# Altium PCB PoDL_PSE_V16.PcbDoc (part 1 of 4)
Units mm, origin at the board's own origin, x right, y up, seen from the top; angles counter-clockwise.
Board outline 155 x 86.5 mm, 4 copper layers (Top Layer, Signal Layer 2, Signal Layer 3, Bottom Layer), stack 1.586 mm thick; 431 components, 281 nets, 1286 pads, 864 vias.
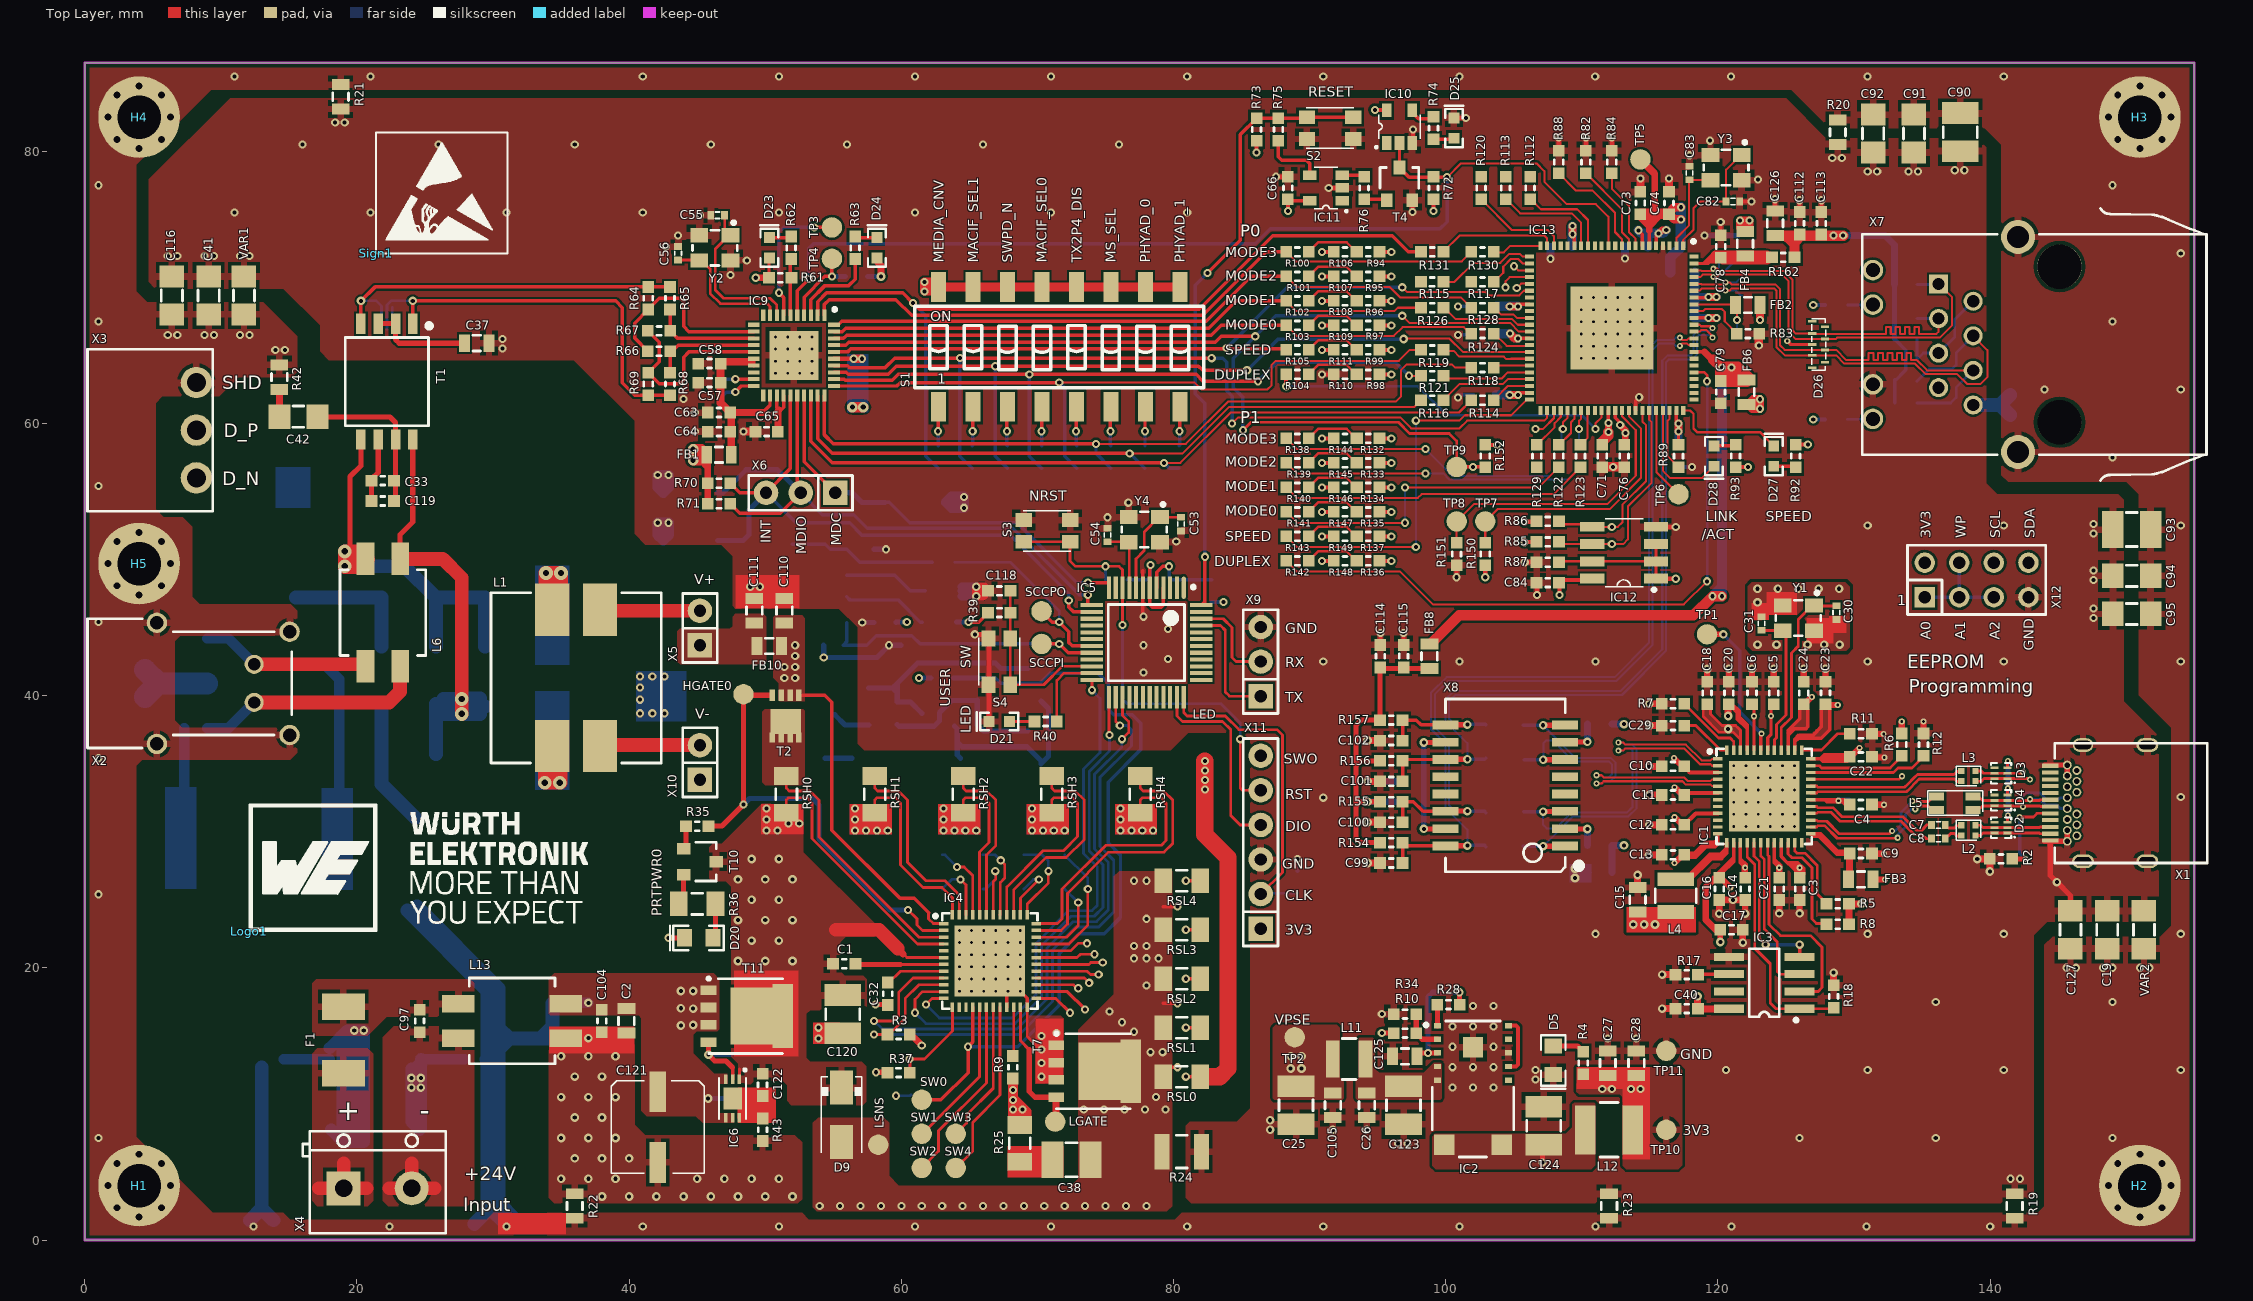
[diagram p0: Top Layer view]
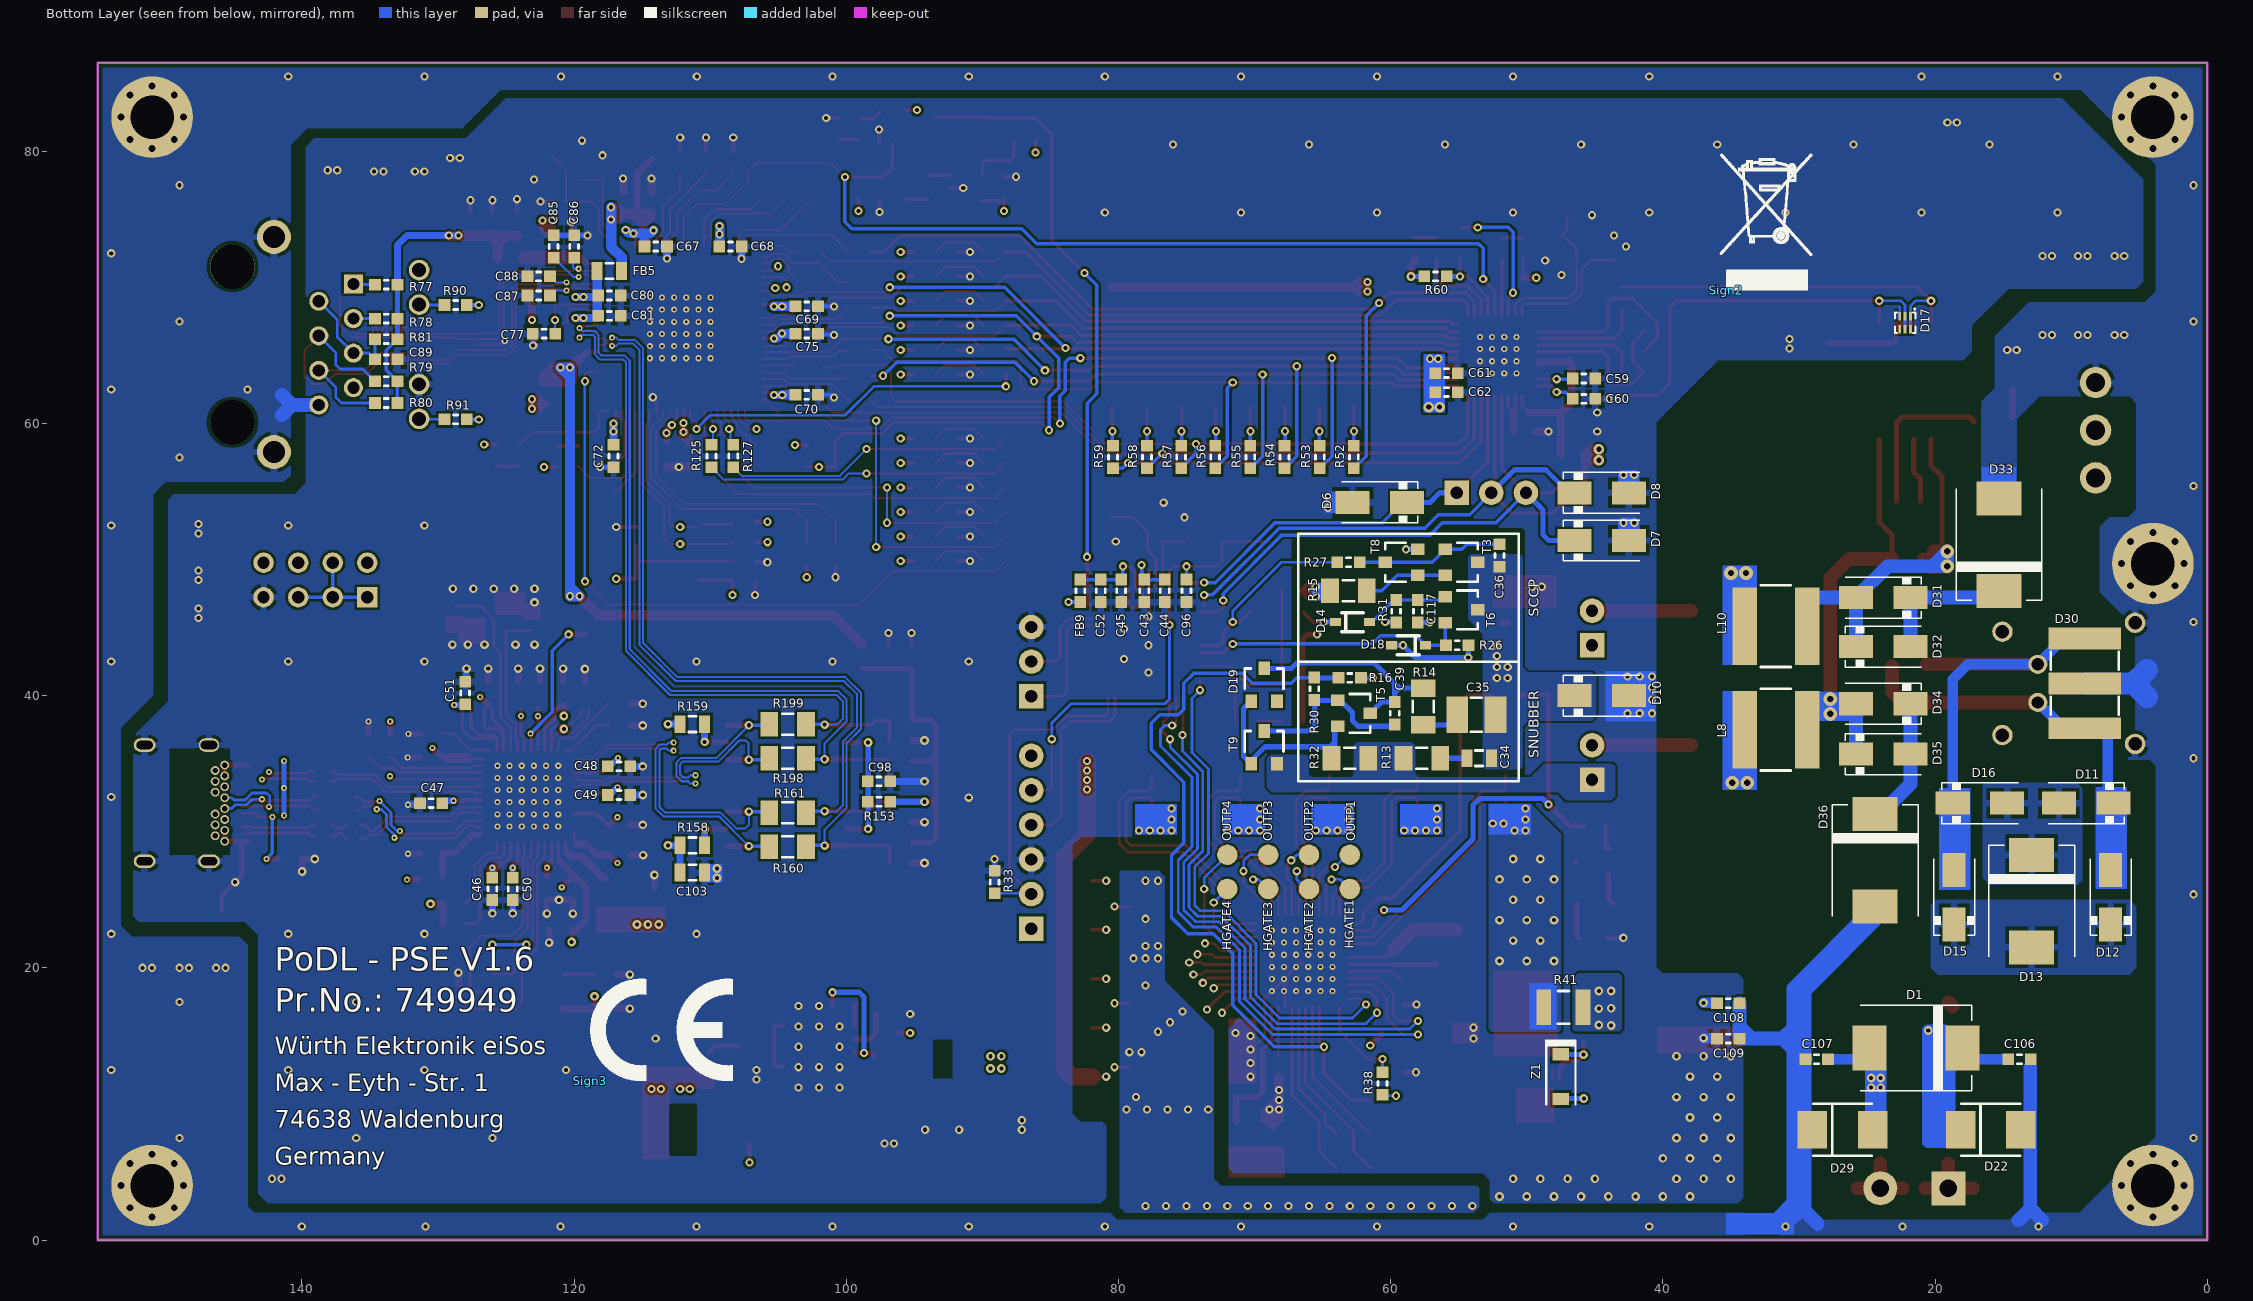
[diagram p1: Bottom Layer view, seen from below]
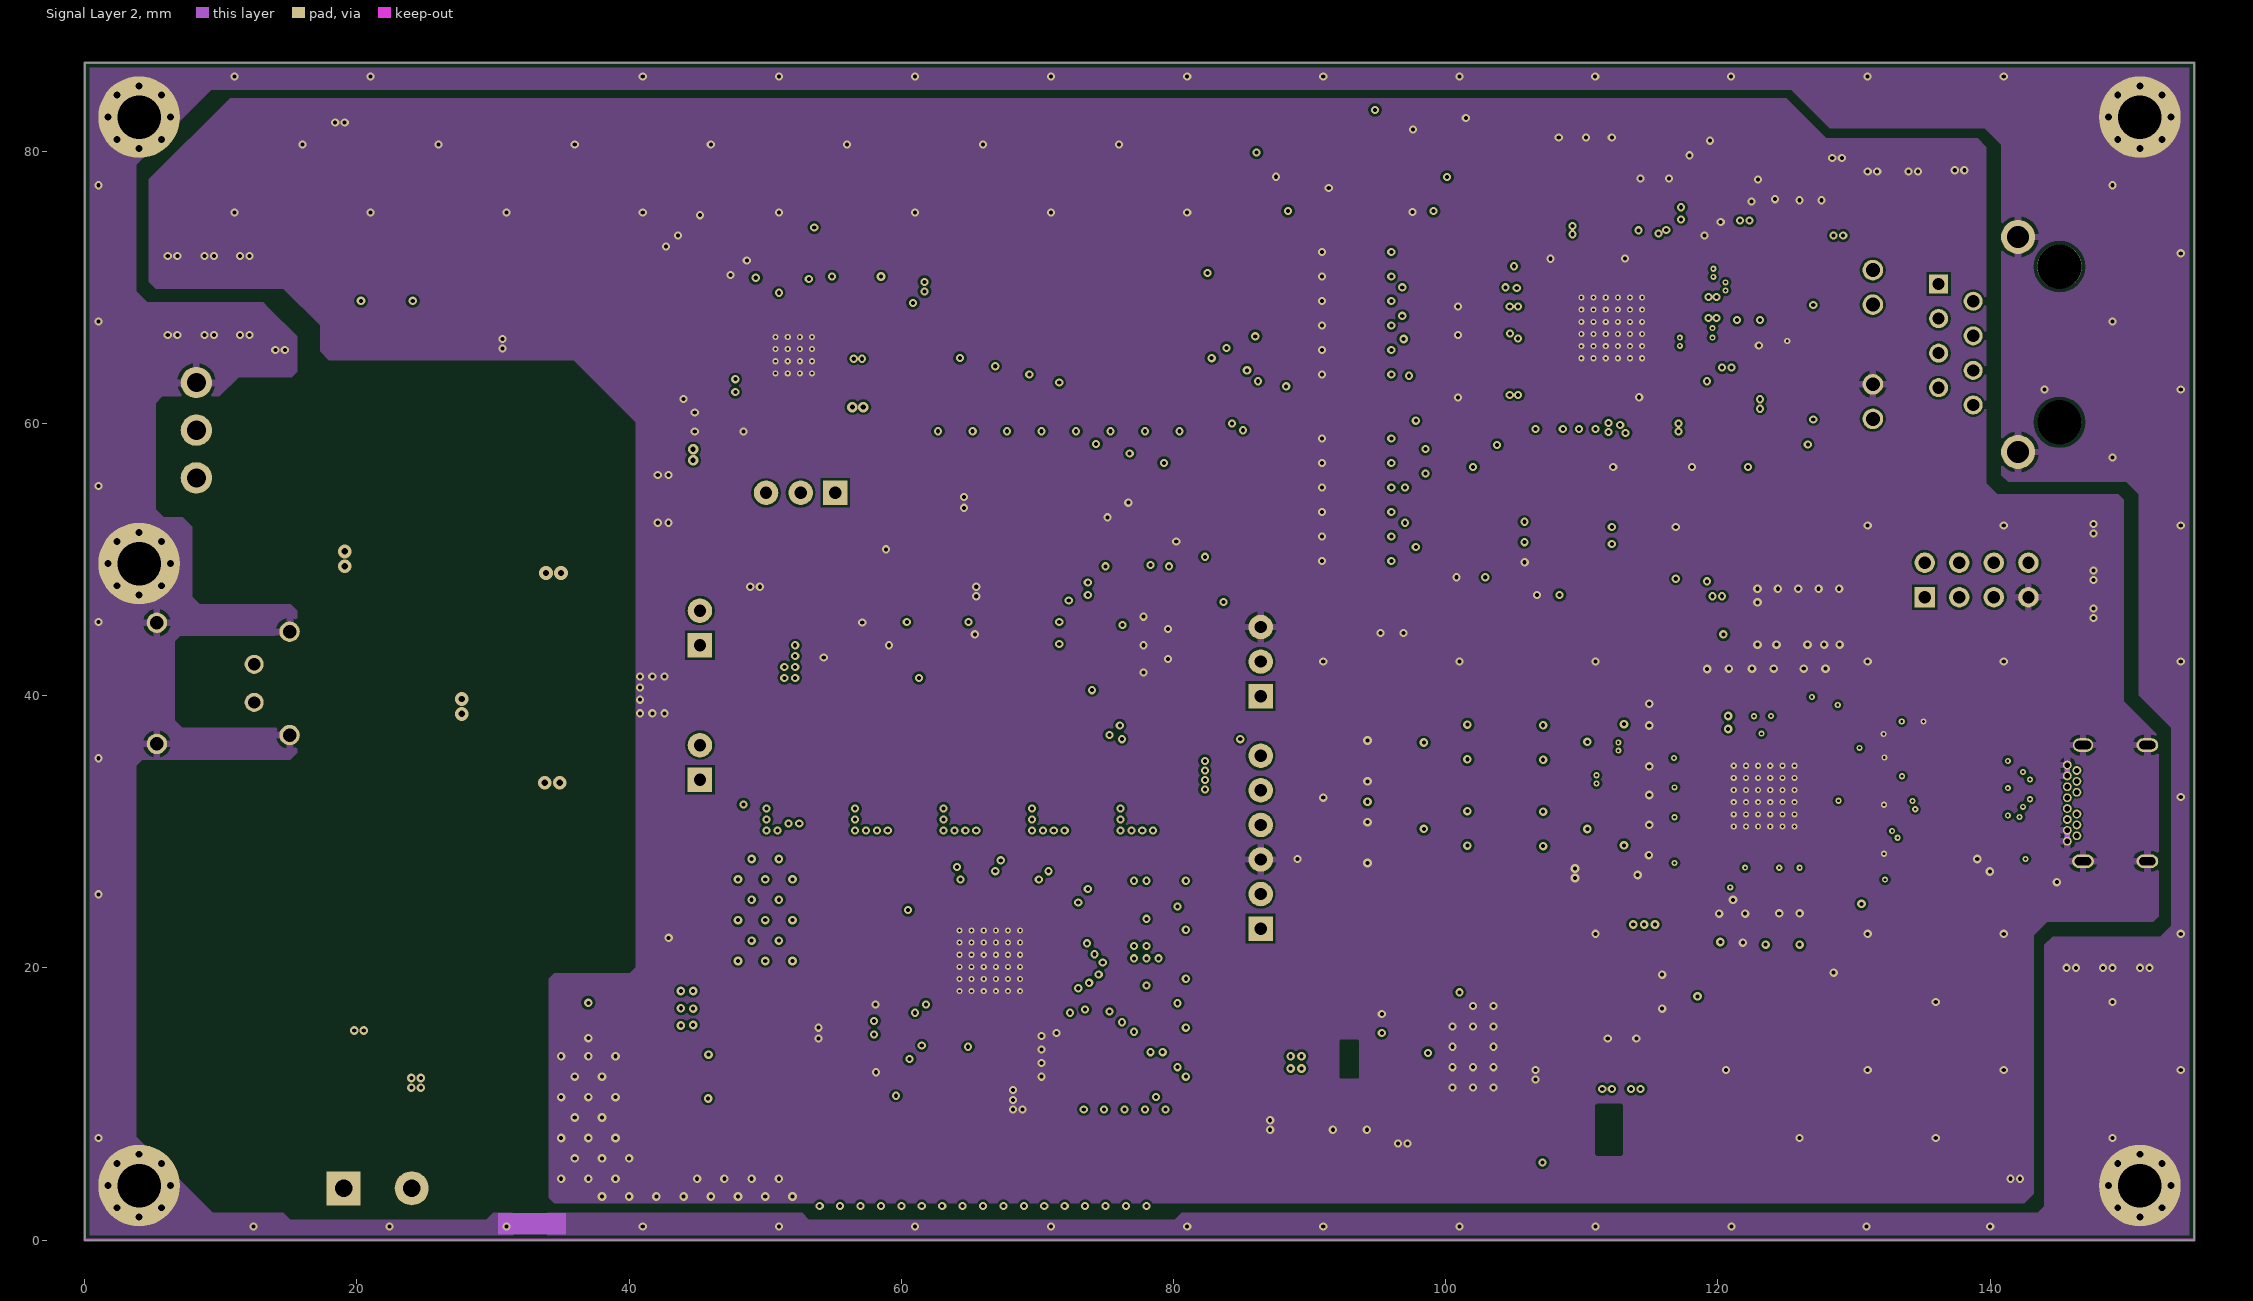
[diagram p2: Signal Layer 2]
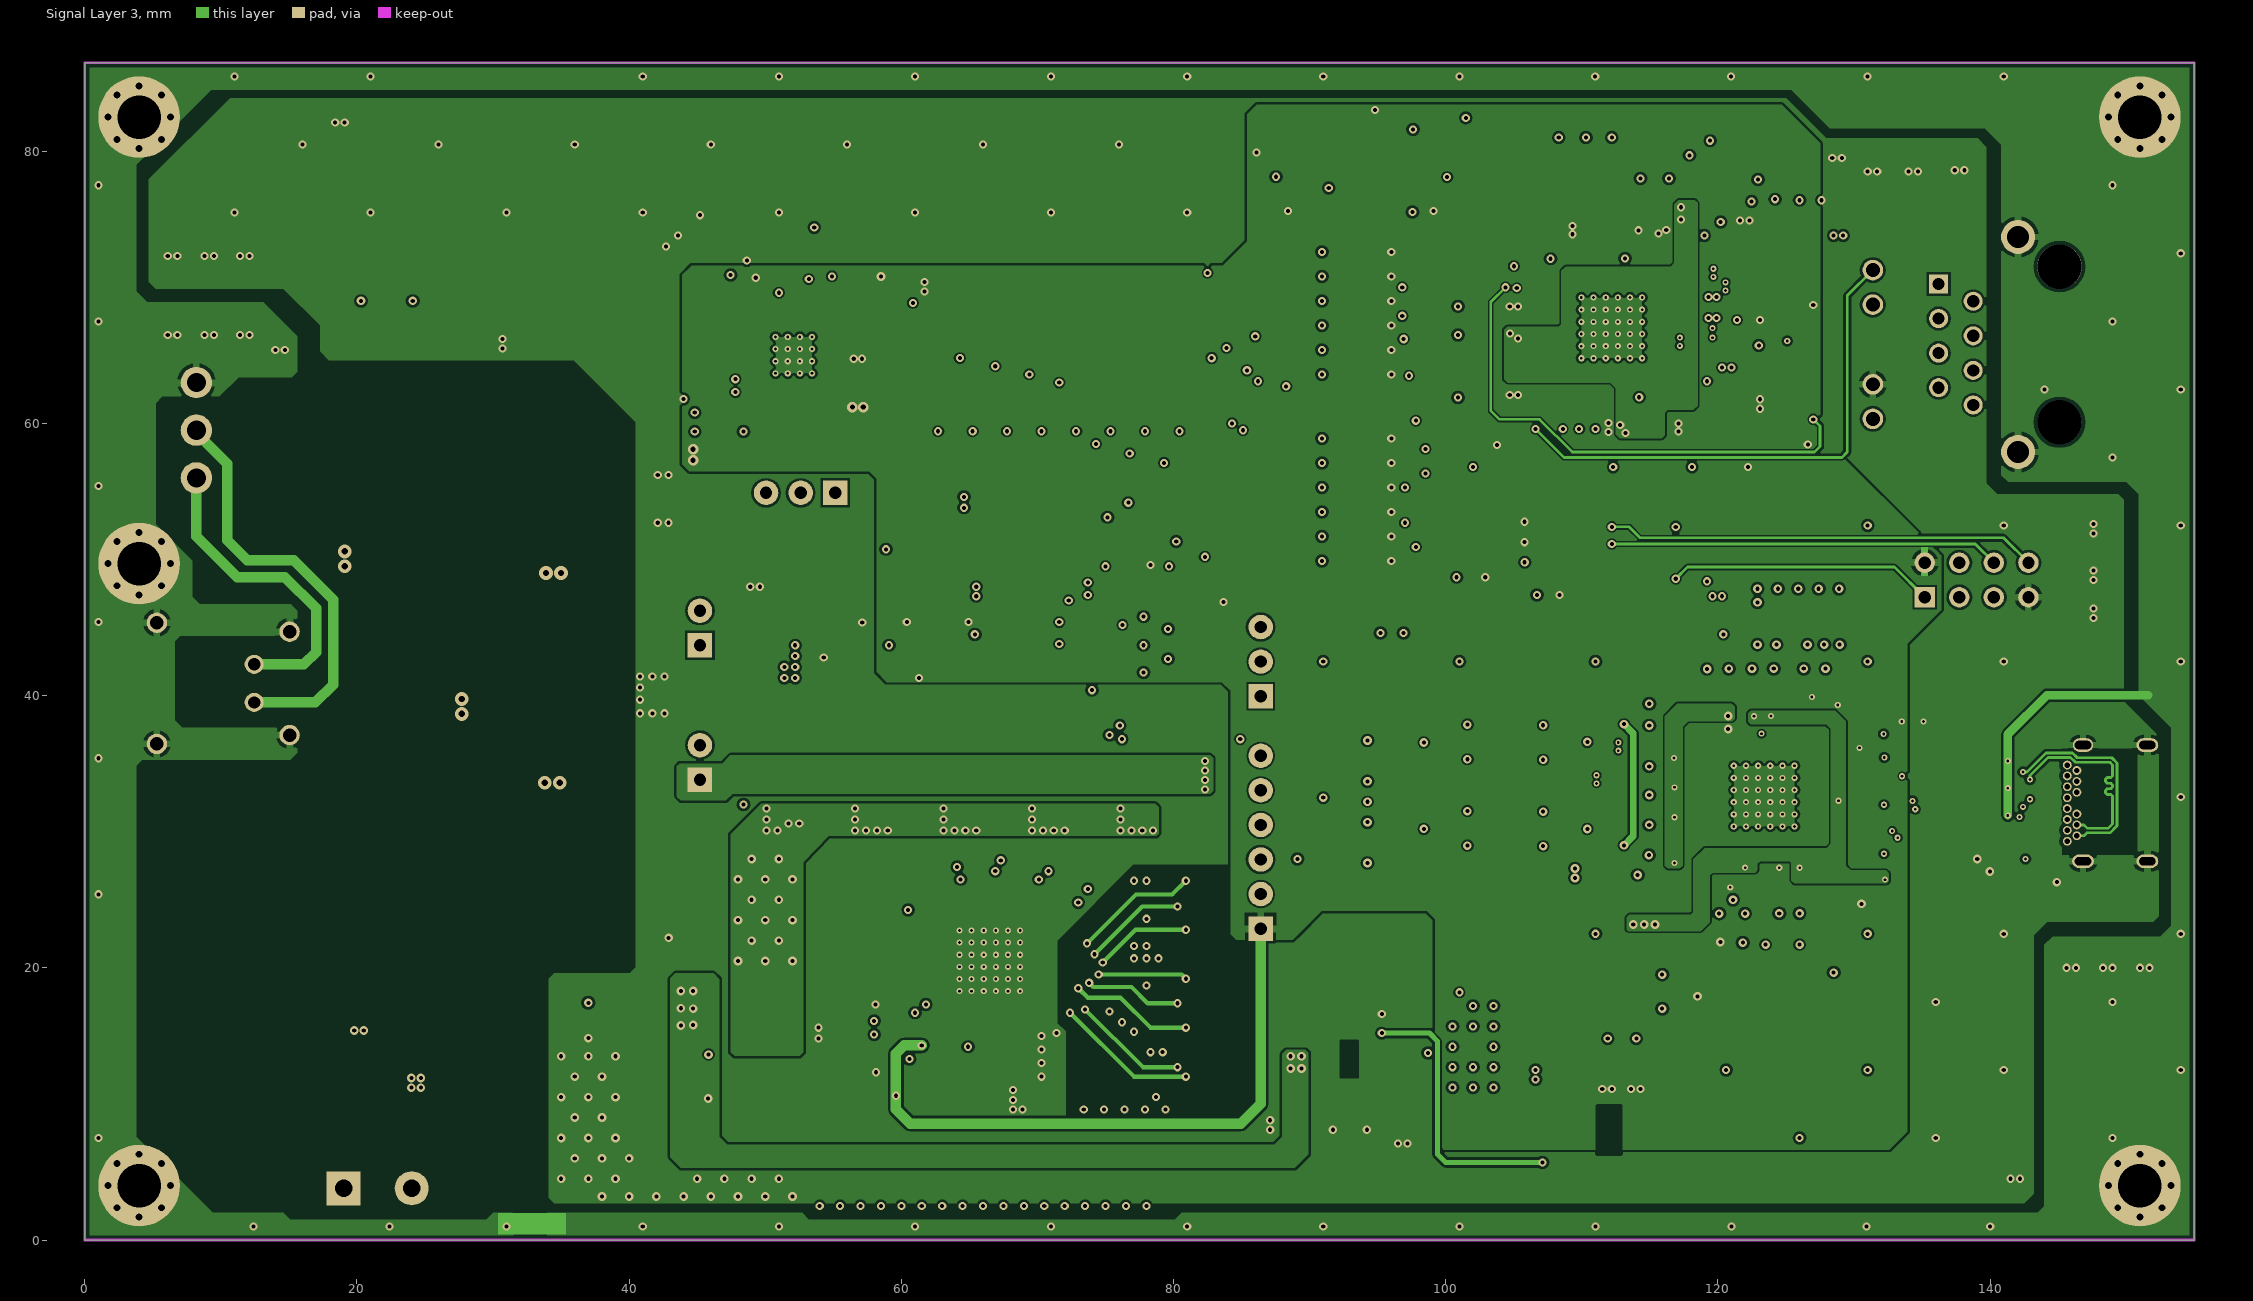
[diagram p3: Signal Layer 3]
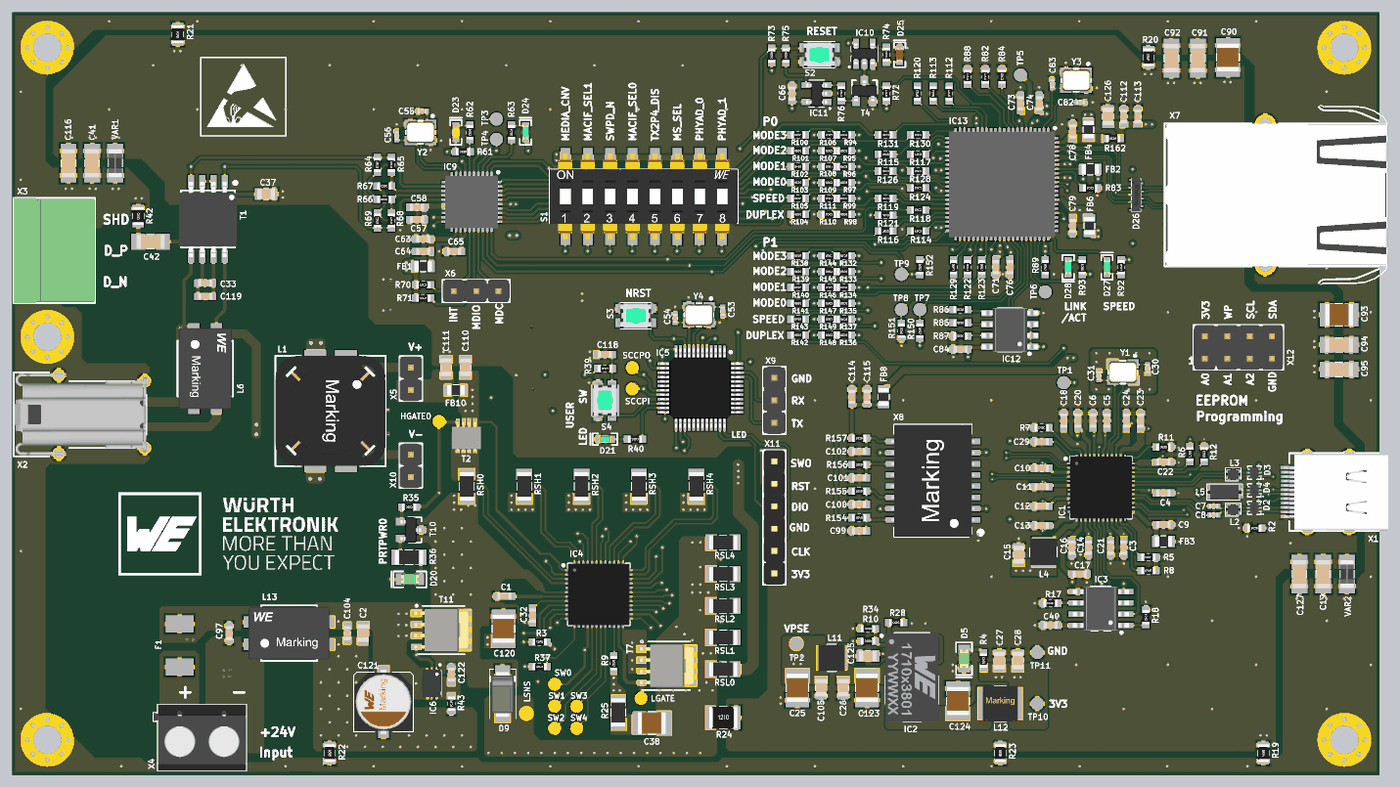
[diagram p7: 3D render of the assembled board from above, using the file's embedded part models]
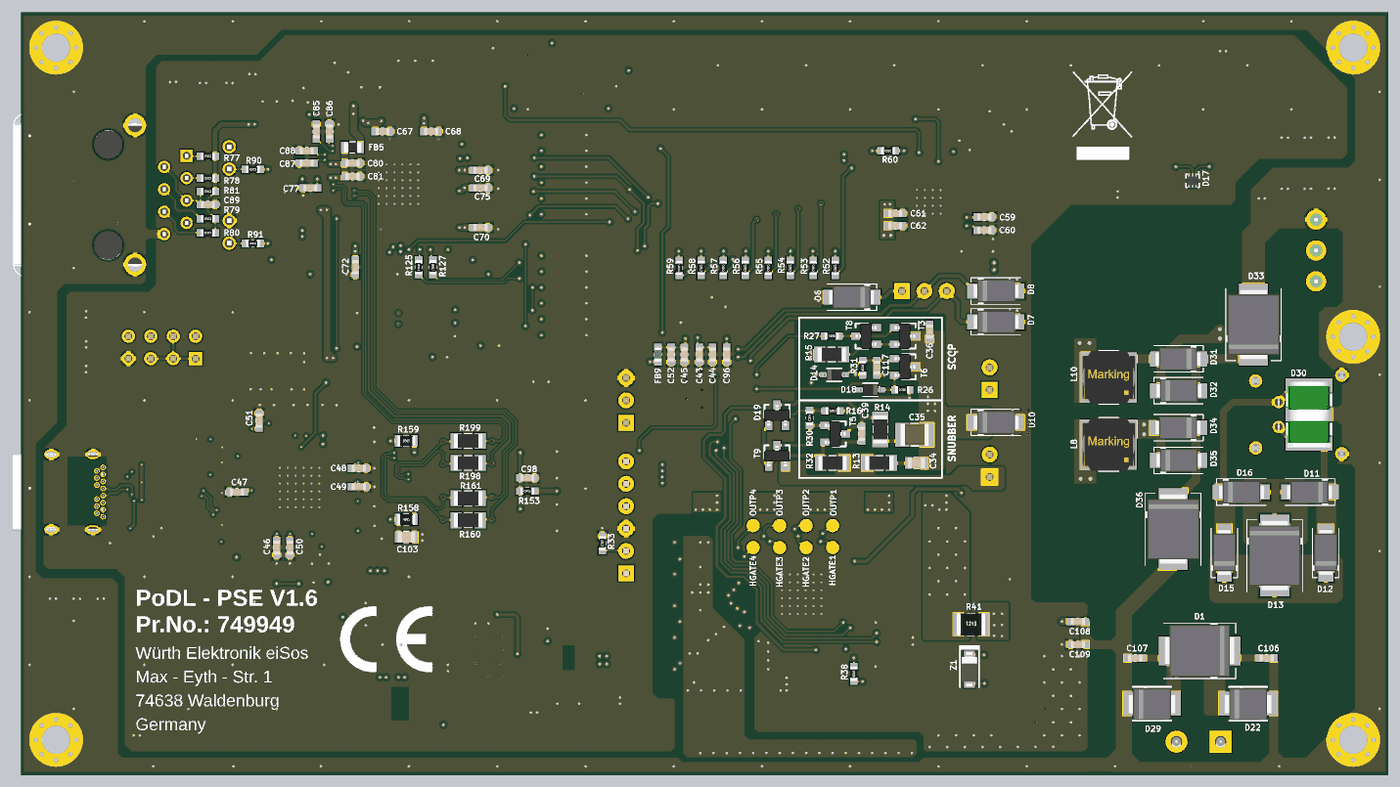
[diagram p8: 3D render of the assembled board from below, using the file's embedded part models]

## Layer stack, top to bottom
Top Solder: solder mask 0.01, Solder Resist, Dk 3.8
Top Layer: signal copper 0.035
Dielectric 1: prepreg 0.2104, 7628, Dk 4.6
Signal Layer 2: signal copper 0.0152
Dielectric 3: core 1.065, Core-009, Dk 4.6
Signal Layer 3: signal copper 0.0152
Dielectric 2: prepreg 0.2104, PP-006, Dk 4.6
Bottom Layer: signal copper 0.035
Bottom Solder: solder mask 0.01, Solder Resist, Dk 3.8

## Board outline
0,0 0,86.5 155,86.5 155,0

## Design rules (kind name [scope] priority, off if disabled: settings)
Clearance USB_to_SHIELD [InDifferentialPairClass('DiffPairs_USB') vs InNet('SHIELD')] p1: gap=0.152 ignorepadtopadclearanceinfootprint=FALSE
Clearance USB-C_Pad [InPadClass('USB-C')] p2: gap=0.127 ignorepadtopadclearanceinfootprint=FALSE
Clearance GND [InNet('GND')] p3: gap=0.178 ignorepadtopadclearanceinfootprint=FALSE
Clearance SHIELD_GND [InNet('SHIELD') vs InNet('GND')] p4: gap=0.483 ignorepadtopadclearanceinfootprint=FALSE
Clearance SHIELD_ALL [InNet('SHIELD')] p5: gap=0.254 ignorepadtopadclearanceinfootprint=FALSE
Clearance Keepout [OnLayer('Keep-Out Layer')] p6: gap=0.381 ignorepadtopadclearanceinfootprint=FALSE
Clearance [All] p7: gap=0.127 ignorepadtopadclearanceinfootprint=FALSE
ComponentClearance USB_Decoupling [InComponentClass('USB-Decoupling') vs InComponentClass('USB-Decoupling')] p1: gap=0 collisioncheckmode=3 verticalgap=0 showdistances=FALSE
ComponentClearance [All] p2: gap=0.254 collisioncheckmode=3 verticalgap=0.254 showdistances=FALSE
DiffPairsRouting DiffPairs_DADA_IN [InDifferentialPairClass('DiffPairs_DATA_IN')] p1: maxlimit=0.203 minlimit=0.203 mostfreqgap=0.203 toplayer_minwidth=0.254 toplayer_maxwidth=1.016 toplayer_prefwidth=0.254 midlayer1_minwidth=0.254 midlayer1_maxwidth=0.762 midlayer1_prefwidth=0.254 midlayer2_minwidth=0.254 midlayer2_maxwidth=0.762 midlayer2_prefwidth=0.254 bottomlayer_minwidth=0.254 bottomlayer_maxwidth=1.016 bottomlayer_prefwidth=0.254 maxuncoupledlength=12.7
DiffPairsRouting DiffPairs_USB [InDifferentialPairClass('DiffPairs_USB')] p2: maxlimit=0.254 minlimit=0.127 mostfreqgap=0.254 toplayer_maxgap=0.127 toplayer_prefgap=0.127 toplayer_minwidth=0.206 toplayer_maxwidth=0.206 toplayer_prefwidth=0.206 midlayer1_maxgap=0.127 midlayer1_prefgap=0.127 midlayer1_minwidth=0.206 midlayer1_maxwidth=0.206 midlayer1_prefwidth=0.206 midlayer2_mingap=0.254 midlayer2_minwidth=0.381 midlayer2_maxwidth=0.381 midlayer2_prefwidth=0.381 bottomlayer_maxgap=0.127 bottomlayer_prefgap=0.127 bottomlayer_minwidth=0.206 bottomlayer_maxwidth=0.206 bottomlayer_prefwidth=0.206 maxuncoupledlength=12.7
DiffPairsRouting DiffPairs_ETH [InDifferentialPairClass('DiffPairs_ETH')] p3: maxlimit=0.254 minlimit=0.127 mostfreqgap=0.254 toplayer_maxgap=0.127 toplayer_prefgap=0.127 toplayer_minwidth=0.154 toplayer_maxwidth=0.254 toplayer_prefwidth=0.154 midlayer1_maxgap=0.127 midlayer1_prefgap=0.127 midlayer1_minwidth=0.154 midlayer1_maxwidth=0.254 midlayer1_prefwidth=0.154 midlayer2_mingap=0.254 midlayer2_minwidth=0.381 midlayer2_maxwidth=0.381 midlayer2_prefwidth=0.381 bottomlayer_maxgap=0.127 bottomlayer_prefgap=0.127 bottomlayer_minwidth=0.154 bottomlayer_maxwidth=0.254 bottomlayer_prefwidth=0.154 maxuncoupledlength=12.7
HoleSize [All] p1: absolutevalues=TRUE maxlimit=5 minlimit=0.025 maxpercent=80.000 minpercent=20.000
MinimumSolderMaskSliver [All] p1 off: minsoldermaskwidth=0.254
NetAntennae [All] p1 off: netantennaetolerance=0
PlaneConnect [All] p1: pad.planeconnectstyle=Relief pad.reliefexpansion=0.508 pad.reliefentries=4 pad.reliefconductorwidth=0.381 pad.reliefairgap=0.203 via.planeconnectstyle=Direct via.reliefexpansion=0.508 via.reliefentries=4 via.reliefconductorwidth=0.254 via.reliefairgap=0.254
PolygonConnect Polygon_NetC124_1 [InNet('NetC124_1')] p1: connectstyle=Direct reliefconductorwidth=0.254 reliefentries=4 polygonreliefangle="90 Angle" airgapwidth=0.254
PolygonConnect Polygon_NetC26_1 [InNet('NetC26_1')] p2: connectstyle=Direct reliefconductorwidth=0.254 reliefentries=4 polygonreliefangle="90 Angle" airgapwidth=0.254
PolygonConnect Polygon_+24V_FILTER [InNet('+24V')] p3: connectstyle=Direct reliefconductorwidth=0.254 reliefentries=4 polygonreliefangle="90 Angle" airgapwidth=0.254
PolygonConnect Polygon_NetIC4_3 [InNet('NetIC4_3')] p4: connectstyle=Direct reliefconductorwidth=0.254 reliefentries=4 polygonreliefangle="90 Angle" airgapwidth=0.254
PolygonConnect Polygon_NetC111_2(OUTP0_FIL) [InNet('NetC111_2')] p5: connectstyle=Direct reliefconductorwidth=0.254 reliefentries=4 polygonreliefangle="90 Angle" airgapwidth=0.254
PolygonConnect Polygon_OUTP0 [InNet('OUTP0')] p6: connectstyle=Direct reliefconductorwidth=0.254 reliefentries=4 polygonreliefangle="90 Angle" airgapwidth=0.254
PolygonConnect Polygon_OUTM0 [InNet('OUTM0')] p7: connectstyle=Direct reliefconductorwidth=0.254 reliefentries=4 polygonreliefangle="90 Angle" airgapwidth=0.254
PolygonConnect Polygo_LSNS [InNet('LSNS')] p8: connectstyle=Direct reliefconductorwidth=0.254 reliefentries=4 polygonreliefangle="90 Angle" airgapwidth=0.254
PolygonConnect PolygonTransformer [InNetClass('Transformer')] p9: connectstyle=Direct reliefconductorwidth=0.254 reliefentries=4 polygonreliefangle="90 Angle" airgapwidth=0.254
PolygonConnect "Polygon_SHIELD_USB_Fix hole" [InPadClass('Fix_Hole') vs InNet('SHIELD_USB')] p10: thpad.connectstyle=Direct thpad.reliefconductorwidth=0.254 thpad.reliefentries=4 thpad.polygonreliefangle="90 Angle" thpad.airgapwidth=0.254 smdpad.connectstyle=Relief smdpad.reliefconductorwidth=0.508 smdpad.reliefentries=4 smdpad.polygonreliefangle="90 Angle" smdpad.airgapwidth=0.254 via.connectstyle=Direct via.reliefconductorwidth=0.254 via.reliefentries=4 via.polygonreliefangle="90 Angle" via.airgapwidth=0.254
PolygonConnect Poly_GND_OSC [InNamedPolygon('GND_OSC') vs InNet('GND')] p11: connectstyle=Direct reliefconductorwidth=0.254 reliefentries=4 polygonreliefangle="90 Angle" airgapwidth=0.254
PolygonConnect "Poly_SHIELD_Fix hole" [InPadClass('Fix_Hole') vs InNet('SHIELD')] p12: thpad.connectstyle=Direct thpad.reliefconductorwidth=0.254 thpad.reliefentries=4 thpad.polygonreliefangle="90 Angle" thpad.airgapwidth=0.254 smdpad.connectstyle=Relief smdpad.reliefconductorwidth=0.508 smdpad.reliefentries=4 smdpad.polygonreliefangle="90 Angle" smdpad.airgapwidth=0.254 via.connectstyle=Direct via.reliefconductorwidth=0.254 via.reliefentries=4 via.polygonreliefangle="90 Angle" via.airgapwidth=0.254
PolygonConnect Poly_SHIELD [All vs InNet('SHIELD')] p13: thpad.connectstyle=Relief thpad.reliefconductorwidth=0.508 thpad.reliefentries=4 thpad.polygonreliefangle="90 Angle" thpad.airgapwidth=0.254 smdpad.connectstyle=Relief smdpad.reliefconductorwidth=0.508 smdpad.reliefentries=4 smdpad.polygonreliefangle="90 Angle" smdpad.airgapwidth=0.254 via.connectstyle=Direct via.reliefconductorwidth=0.254 via.reliefentries=4 via.polygonreliefangle="90 Angle" via.airgapwidth=0.254
PolygonConnect [All] p14: thpad.connectstyle=Relief thpad.reliefconductorwidth=0.508 thpad.reliefentries=4 thpad.polygonreliefangle="90 Angle" thpad.airgapwidth=0.254 smdpad.connectstyle=Relief smdpad.reliefconductorwidth=0.508 smdpad.reliefentries=4 smdpad.polygonreliefangle="90 Angle" smdpad.airgapwidth=0.254 via.connectstyle=Direct via.reliefconductorwidth=0.254 via.reliefentries=4 via.polygonreliefangle="90 Angle" via.airgapwidth=0.254
RoutingVias [All] p1: holewidth=0.2 width=0.5 viastyle="Through Hole" minholewidth=0.2 minwidth=0.45 maxholewidth=0.711 maxwidth=1.27
SilkToSilkClearance [All] p1 off: silktosilkclearance=0.254
SilkToSolderMaskClearance [IsPad] p1 off: minsilkscreentomaskgap=0.254 clearancetoexposedcopper=TRUE
SolderMaskExpansion [All] p1: expansion=0.102
Width [All] p1: maxlimit=2.54 minlimit=0.127 preferedwidth=0.254 minimp=50.000000 maximp=50.000000 favimp=50.000000
22 further rules are at their usual default settings.

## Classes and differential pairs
component class USB-Decoupling: L6
component class U_01-PSE_Power_MCU: C1 C2 C25 C26 C27 C28 C32 C33 C34 C35 C36 C37 C38 C39 C41 C42 C43 C44 C45 C52 C53 C54 C96 C97 C104 C105 C106 C107 C108 C109 C110 C111 C116 C117 C118 C119 C120 C121 C122 C123 C124 C125 D1 D5 D9 D10 D11 D12 D13 D14 D15 D16 D17 D18 D19 D20 D21 D22 D29 D30 D31 D32 D33 D34 D35 D36 F1 FB9 FB10 H1 H2 H3 H4 H5 HGATE0 HGATE1 HGATE2 HGATE3 HGATE4 IC2 IC4 IC5 IC6 L1 L6 L8 L10 L11 L12 L13 LGATE Logo1 LSNS OUTP1 OUTP2 OUTP3 OUTP4 R3 R4 R9 R10 R13 R14 R15 R16 R19 R20 R21 R22 R23 R24 R25 R26 R27 R28 R30 R31 R32 R33 R34 R35 R36 R37 R38 R39 R40 R41 R42 R43 RSH0 RSH1 RSH2 RSH3 RSH4 RSL0 RSL1 RSL2 RSL3 RSL4 S3 S4 SCCPI SCCPO Sign1 Sign2 Sign3 SW0 SW1 SW2 SW3 SW4 T1 T2 T3 T5 T6 T7 T8 T9 T10 T11 TP2 TP10 TP11 VAR1 X2 X3 X4 X5 X9 X10 X11 Y4 Z1
differential pair class DiffPairs_DATA_IN: POWER/DATA
differential pair class DiffPairs_ETH: RXA TR0 TR1 TXA
differential pair class DiffPairs_USB: D USB2D USB2D1 USB3RX USB3RX1 USB3TX USB3TX1
component class U_04-LAN_to_USB-C: C3 C4 C5 C6 C7 C8 C9 C10 C11 C12 C13 C14 C15 C16 C17 C18 C19 C20 C21 C22 C23 C24 C29 C30 C31 C40 C46 C47 C48 C49 C50 C51 C98 C99 C100 C101 C102 C103 C114 C115 C127 D2 D3 D4 FB3 FB8 IC1 IC3 L2 L3 L4 L5 R2 R5 R6 R7 R8 R11 R12 R17 R18 R153 R154 R155 R156 R157 R158 R159 R160 R161 R198 R199 TP1 VAR2 X1 X8 Y1
component class U_03-LAN_3-Ports_Switch: C66 C67 C68 C69 C70 C71 C72 C73 C74 C75 C76 C77 C78 C79 C80 C81 C82 C83 C84 C85 C86 C87 C88 C89 C90 C91 C92 C93 C94 C95 C112 C113 C126 D25 D26 D27 D28 FB2 FB4 FB5 FB6 IC10 IC11 IC12 IC13 R72 R73 R74 R75 R76 R77 R78 R79 R80 R81 R82 R83 R84 R85 R86 R87 R88 R89 R90 R91 R92 R93 R94 R95 R96 R97 R98 R99 R100 R101 R102 R103 R104 R105 R106 R107 R108 R109 R110 R111 R112 R113 R114 R115 R116 R117 R118 R119 R120 R121 R122 R123 R124 R125 R126 R127 R128 R129 R130 R131 R132 R133 R134 R135 R136 R137 R138 R139 R140 R141 R142 R143 R144 R145 R146 R147 R148 R149 R150 R151 R152 R162 S2 T4 TP5 TP6 TP7 TP8 TP9 X7 X12 Y3
component class U_02-10BASE-T1L_PHY: C55 C56 C57 C58 C59 C60 C61 C62 C63 C64 C65 D6 D7 D8 D23 D24 FB1 IC9 R52 R53 R54 R55 R56 R57 R58 R59 R60 R61 R62 R63 R64 R65 R66 R67 R68 R69 R70 R71 S1 TP3 TP4 X6 Y2
pad class USB-C: X1-B1 X1-B2 X1-B3 X1-B4 X1-B5 X1-B6 X1-B7 X1-B8 X1-B9 X1-B10 X1-B11 X1-B12
pad class Fix_Hole: H1-0 H2-0 H3-0 H4-0 H5-0
differential pair USB3TX: +USB3TX_P -USB3TX_N
differential pair USB3TX1: +USB3TX1_P -USB3TX1_N
differential pair USB3RX: +USB3RX_P -USB3RX_N
differential pair USB3RX1: +USB3RX1_P -USB3RX1_N
differential pair USB2D: +USB2D_P -USB2D_N
differential pair USB2D1: +USB2D1_P -USB2D1_N
differential pair TXB: +TXB_P -TXB_N
differential pair TXA: +TXA_P -TXA_N
differential pair TR1: +TR1_P -TR1_N
differential pair TR0: +TR0_P -TR0_N
differential pair RXB: +RXB_P -RXB_N
differential pair RXA: +RXA_P -RXA_N
differential pair POWER/DATA: +POWER/DATA_P -POWER/DATA_N
differential pair D: +D_P -D_N

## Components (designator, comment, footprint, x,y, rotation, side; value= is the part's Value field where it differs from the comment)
C1 "885012206083" CC1608-0603 55.8,20.3 r0 top value=1nF
C2 "885012207103" CC2012-0805 39.8,16.1 r270 top value=1uF
C3 "885012206071" CC1608-0603 126,25.8 r270 top value=100nF
C4 "885012206071" CC1608-0603 130.5,32 r0 top value=100nF
C5 "885012206071" CC1608-0603 124.1,40.2 r90 top value=100nF
C6 "885012206071" CC1608-0603 122.5,40.2 r90 top value=100nF
C7 "885012105018" CC1005-0402 136.2,30.5 r180 top value=100nF
C8 "885012105018" CC1005-0402 136.2,29.5 r180 top value=100nF
C9 "885012206052" CC1608-0603 130.5,28.4 r0 top value=1uF
C10 "885012206071" CC1608-0603 116.7,34.8 r180 top value=100nF
C11 "885012206071" CC1608-0603 116.7,32.7 r180 top value=100nF
C12 "885012206071" CC1608-0603 116.7,30.5 r180 top value=100nF
C13 "885012206071" CC1608-0603 116.7,28.3 r180 top value=100nF
C14 "885012206071" CC1608-0603 122,25.8 r270 top value=100nF
C15 "885012107005" CC2012-0805 114.1,25 r270 top value=22uF
C16 "885012206071" CC1608-0603 120.1,25.8 r270 top value=100nF
C17 "885012106006" CC1608-0603 121,22.8 r180 top value=10uF
C18 "885012206052" CC1608-0603 119.2,40.2 r90 top value=1uF
C19 "885012208112" CC3216-1206 148.6,22.8 r270 top value=10nF
C20 "885012206052" CC1608-0603 120.8,40.2 r90 top value=1uF
C21 "885012206071" CC1608-0603 124.5,25.8 r270 top value=100nF
C22 "885012206071" CC1608-0603 130.5,35.5 r0 top value=100nF
C23 "885012206071" CC1608-0603 127.9,40.2 r90 top value=100nF
C24 "885012206071" CC1608-0603 126.3,40.2 r90 top value=100nF
C25 "885012209073" CC3225-1210 89,9.9 r270 top value=10uF
C26 "885012207098" CC2012-0805 94.2,9.9 r270 top value=100nF
C27 "885012207026" CC2012-0805 111.9,13 r90 top value=10uF
C28 "885012207026" CC2012-0805 114,13 r90 top value=10uF
C29 "885012206052" CC1608-0603 116.7,37.8 r180 top value=1uF
C30 "885012005056" CC1005-0402 128.7,46.1 r90 top value=15pF
C31 "885012005056" CC1005-0402 123.2,45.3 r270 top value=15pF
C32 "885012206024" CC1608-0603 59,18.1 r270 top value=470nF
C33 "885012206120" CC1608-0603 21.9,55.8 r0 top value=100nF
C34 "885012207098" CC2012-0805 53.5,35.4 r0 bottom value=100nF
C35 "885382209002" CC3225-1210 53.7,38.6 r0 bottom value=2.2uF
C36 "885012206085" CC1608-0603 52,50.3 r270 bottom value=2.2nF
C37 "885012207098" CC2012-0805 28.8,65.9 r0 top value=100nF
C38 "885382209002" CC3225-1210 72.5,5.9 r180 top value=2.2uF
C39 "885012206085" CC1608-0603 59.7,38.7 r90 bottom value=2.2nF
C40 "885012206071" CC1608-0603 117.7,17 r180 top value=100nF
C41 "885012208112" CC3216-1206 9.1,69.4 r90 top value=10nF
C42 "885342208021" CC3216-1206 15.7,60.5 r180 top value=10nF
C43 "885012106012" CC1608-0603 78.1,47.7 r270 bottom value=4.7uF
C44 "885012206071" CC1608-0603 76.6,47.7 r270 bottom value=100nF
C45 "885012206040" CC1608-0603 79.8,47.7 r270 bottom value=10nF
C46 "885012206071" CC1608-0603 126,25.8 r270 bottom value=100nF
C47 "885012206071" CC1608-0603 130.5,32.1 r0 bottom value=100nF
C48 "885012206071" CC1608-0603 116.7,34.8 r180 bottom value=100nF
C49 "885012206071" CC1608-0603 116.7,32.7 r180 bottom value=100nF
C50 "885012206071" CC1608-0603 124.5,25.8 r270 bottom value=100nF
C51 "885012206071" CC1608-0603 128,40.2 r90 bottom value=100nF
C52 "885012206052" CC1608-0603 81.3,47.7 r270 bottom value=1uF
C53 "885012005056" CC1005-0402 80.55,52.6 r90 top value=15pF
C54 "885012005056" CC1005-0402 75.15,51.8 r270 top value=15pF
C55 "885012005056" CC1005-0402 46.5,75.3 r0 top value=15pF
C56 "885012005056" CC1005-0402 43.6,72.5 r270 top value=15pF
C57 "885012206071" CC1608-0603 45.9,63 r180 top value=100nF
C58 "885012206040" CC1608-0603 45.9,64.4 r180 top value=10nF
C59 "885012206071" CC1608-0603 45.8,63.3 r180 bottom value=100nF
C60 "885012206052" CC1608-0603 45.8,61.8 r180 bottom value=1uF
C61 "885012206040" CC1608-0603 55.9,63.7 r180 bottom value=10nF
C62 "885012206071" CC1608-0603 55.9,62.3 r180 bottom value=100nF
C63 "885012206071" CC1608-0603 46.6,60.8 r180 top value=100nF
C64 "885012206040" CC1608-0603 46.6,59.4 r180 top value=10nF
C65 "885012206051" CC1608-0603 50.1,59.4 r180 top value=680nF
C66 "885012206071" CC1608-0603 88.4,77.3 r270 top value=100nF
C67 "885012206071" CC1608-0603 114,73 r180 bottom value=100nF
C68 "885012206071" CC1608-0603 108.5,73 r180 bottom value=100nF
C69 "885012206071" CC1608-0603 102.9,68.6 r180 bottom value=100nF
C70 "885012206071" CC1608-0603 102.9,62.1 r180 bottom value=100nF
C71 "885012206071" CC1608-0603 111.5,57.6 r270 top value=100nF
C72 "885012206071" CC1608-0603 117.1,57.6 r270 bottom value=100nF
C73 "885012206026" CC1608-0603 114.3,76.2 r270 top value=1uF
C74 "885012206081" CC1608-0603 116.4,76.2 r90 top value=470pF
C75 "885012206071" CC1608-0603 102.9,66.6 r180 bottom value=100nF
C76 "885012206071" CC1608-0603 113.1,57.6 r270 top value=100nF
C77 "885012206071" CC1608-0603 122.2,66.6 r0 bottom value=100nF
C78 "885012206071" CC1608-0603 120.2,73 r90 top value=100nF
C79 "885012206071" CC1608-0603 120.2,62.3 r270 top value=100nF
C80 "885012206071" CC1608-0603 117.4,69.4 r180 bottom value=100nF
C81 "885012206071" CC1608-0603 117.4,67.9 r180 bottom value=100nF
C82 "885012005056" CC1005-0402 121.1,76.3 r180 top value=15pF
C83 "885012005056" CC1005-0402 117.9,78.4 r270 top value=15pF
C84 "885012206071" CC1608-0603 107.5,48.3 r0 top value=100nF
C85 "885012006051" CC1608-0603 121.5,73 r90 bottom value=10pF
C86 "885012006051" CC1608-0603 120,73 r90 bottom value=10pF
C87 "885012006051" CC1608-0603 122.6,69.4 r0 bottom value=10pF
C88 "885012006051" CC1608-0603 122.6,70.8 r0 bottom value=10pF
C89 "885012206091" CC1608-0603 133.8,64.7 r180 bottom value=22nF
C90 "" CC3225-1210 137.8,81.4 r270 top value=TBE
C91 "" CC3216-1206 134.4,81.3 r270 top value=TBE
C92 "" CC3216-1206 131.4,81.3 r270 top value=TBE
C93 "" CC3225-1210 150.4,52.2 r180 top value=TBE
C94 "" CC3216-1206 150.4,48.8 r180 top value=TBE
C95 "" CC3216-1206 150.4,46 r180 top value=TBE
C96 "885012206071" CC1608-0603 75,47.7 r270 bottom value=100nF
C97 "885012206114" CC1608-0603 24.6,16.1 r270 top value=10nF
C98 "885012206091" CC1608-0603 97.6,33.7 r180 bottom value=22nF
C99 "885012006051" CC1608-0603 96,27.7 r180 top value=10pF
C100 "885012006051" CC1608-0603 96,30.7 r180 top value=10pF
C101 "885012006051" CC1608-0603 96,33.7 r180 top value=10pF
C102 "885012006051" CC1608-0603 96,36.7 r180 top value=10pF
C103 "885012207116" CC2012-0805 111.3,27 r180 bottom value=1nF
C104 "885012206114" CC1608-0603 38,16.1 r270 top value=10nF
C105 "885012207098" CC2012-0805 91.7,9.9 r270 top value=100nF
C106 "885012206114" CC1608-0603 13.8,13.279 r180 bottom value=10nF
C107 "885012206114" CC1608-0603 28.7,13.279 r0 bottom value=10nF
C108 "885012206114" CC1608-0603 35.2,17.4 r180 bottom value=10nF
C109 "885012206114" CC1608-0603 35.2,14.8 r180 bottom value=10nF
C110 "885342207005" CC2012-0805 51.4,46.25 r270 top value=10nF
C111 "885342207005" CC2012-0805 49.2,46.25 r270 top value=10nF
C112 "885012206093" CC1608-0603 126,74.7 r90 top value=47nF
C113 "885012206093" CC1608-0603 127.6,74.7 r90 top value=47nF
C114 "885012206093" CC1608-0603 95.2,42.9 r90 top value=47nF
C115 "885012206093" CC1608-0603 96.9,42.9 r90 top value=47nF
C116 "885012208112" CC3216-1206 6.4,69.4 r90 top value=10nF
C117 "" CC1608-0603 58,46.2 r270 bottom value=TBE
C118 "885012206071" CC1608-0603 67.2,47.7 r180 top value=100nF
C119 "885012206120" CC1608-0603 21.9,54.3 r0 top value=100nF
C120 "885012209073" CC3225-1210 55.7,16.6 r270 top value=10uF
C121 "865080643008" "SMT 6.3mmx5.5mm - WE" 42.1,8.3 r0 top value=22uF
C122 "885012206093" CC1608-0603 49.8,11.4 r270 top value=47nF
C123 "885012209048" CC3225-1210 96.9,9.9 r270 top value=4.7uF
C124 "885012209048" CC3225-1210 107.2,8.4 r90 top value=4.7uF
C125 "885012207051" CC2012-0805 97,13.5 r180 top value=1uF
C126 "885012007063" CC2012-0805 124.2,74.7 r90 top value=1nF
C127 "885012208112" CC3216-1206 145.9,22.8 r270 top value=10nF
D1 "824541331" SMC/DO-214AB 21.4,14.1 r180 bottom
D2 "824012823" "DFN1210-6L 1.2X1.0" 140.8,30.3 r90 top
D3 "824012823" "DFN1210-6L 1.2X1.0" 140.8,34.3 r90 top
D4 "824012823" "DFN1210-6L 1.2X1.0" 140.8,32.3 r90 top
D5 "150080VS75000" "LED2012 (0805) - Green" 107.9,13.2 r90 top value=Green
D6 "824500500" SMA/DO-214AC 60.8,54.2 r180 bottom
D7 "824500500" SMA/DO-214AC 44.5,51.4 r0 bottom
D8 "824500500" SMA/DO-214AC 44.5,54.9 r0 bottom
D9 "S1B-13-F" SMA/DO-214AC 55.6,9.2 r90 top
D10 "S1B-13-F" SMA/DO-214AC 44.5,40 r0 bottom
D11 "S1B-13-F" SMA/DO-214AC 8.9,32.1 r180 bottom
D12 "S1B-13-F" SMA/DO-214AC 7.1,25.2 r270 bottom
D13 "824541361" SMC/DO-214AB 12.9,24.9 r90 bottom
D14 "BAT54WS-7-F" SOD-323 62.8,45.4 r0 bottom value=BAT54WS
D15 "S1B-13-F" SMA/DO-214AC 18.6,25.2 r270 bottom
D16 "S1B-13-F" SMA/DO-214AC 16.7,32.1 r0 bottom
D17 "824012823" "DFN1210-6L 1.2X1.0" 22.2,67.4 r0 bottom
D18 "BAT54WS-7-F" SOD-323 58.7,43.7 r180 bottom value=BAT54WS
D19 "MMBD914LT1G" SOT-23 69.3,40.8 r180 bottom value=MMBD914L
D20 "150080VS75000" "LED2012 (0805) - Green" 45.1,22.2 r0 top value=Green
D21 "150060BS55040" "LED1608 (0603) - BLUE" 67.2,38.1 r0 top value=Blue
D22 "824520241" SMB/DO-214AA 15.9,8.1 r0 bottom
D23 "LTST-C190KSKT" "LED1608 (0603) - YELLOW" 50.3,72.9 r270 top value=Yellow
D24 "150060VS75020" "LED1608 (0603) - Green" 58.2,72.9 r270 top value=Green
D25 "150060SS75020" "LED1608 (0603) - Red" 100.6,81.7 r270 top value=Red
D26 "824014885" WE-TVS_824014885 127.4,65.8 r270 top
D27 "150060VS75020" "LED1608 (0603) - Green" 124.1,57.6 r270 top value=Green
D28 "150060VS75020" "LED1608 (0603) - Green" 119.7,57.6 r90 top value=Green
D29 "824520241" SMB/DO-214AA 26.8,8.1 r0 bottom
D30 "2038-15-SM-RPLF" 2038-XX 9,40.9 r90 bottom value=150V
D31 "S1D-13-F" SMA/DO-214AC 23.8,47.2 r180 bottom
D32 "S1D-13-F" SMA/DO-214AC 23.8,43.6 r0 bottom
D33 "824541361" SMC/DO-214AB 15.3,51.1 r270 bottom
D34 "S1D-13-F" SMA/DO-214AC 23.8,39.4 r180 bottom
D35 "S1D-13-F" SMA/DO-214AC 23.8,35.7 r0 bottom
D36 "824541361" SMC/DO-214AB 24.4,27.9 r90 bottom
F1 "0454002.MR" SET 19,14.7 r90 top
FB1 "742792031" CF2012-0805 46.6,57.7 r0 top value=300R@100MHz
FB2 "742792031" CF2012-0805 122.2,68.7 r180 top value=300R@100MHz
FB3 "742792031" CF2012-0805 130.5,26.5 r0 top value=300R
FB4 "742792031" CF2012-0805 122,73.2 r270 top value=300R@100MHz
FB5 "742792031" CF2012-0805 117.4,71.2 r180 bottom value=300R@100MHz
FB6 "742792031" CF2012-0805 122.1,62.3 r90 top value=300R@100MHz
FB8 "742792040" CF2012-0805 98.8,42.9 r90 top value=600R@100MHz
FB9 "742792625" CF1608-0603 82.8,47.7 r270 bottom value=120R
FB10 "742792031" CF2012-0805 50.3,43.65 r180 top value=300R@100MHz
H1 "Hole M3 with Vias" M3_VIA 4,4 r0 top
H2 "Hole M3 with Vias" M3_VIA 151,4 r0 top
H3 "Hole M3 with Vias" M3_VIA 151,82.5 r0 top
H4 "Hole M3 with Vias" M3_VIA 4,82.5 r0 top
H5 "Hole M3 with Vias" M3_VIA 4,49.7 r90 top
HGATE0 "PartNumber" "TESTPOINT 1.5mm"#1 48.4,40.1 r90 top value=1.5mm
HGATE1 "PartNumber" "TESTPOINT 1.5mm"#1 63,25.8 r90 bottom value=1.5mm
HGATE2 "PartNumber" "TESTPOINT 1.5mm"#1 66,25.8 r90 bottom value=1.5mm
HGATE3 "PartNumber" "TESTPOINT 1.5mm"#1 69,25.8 r90 bottom value=1.5mm
HGATE4 "PartNumber" "TESTPOINT 1.5mm"#1 72,25.8 r90 bottom value=1.5mm
IC1 "LAN7800/Y9X" "QFN-48 7x7MM" 123.4,32.6 r0 top value=LAN7800
IC2 "171033801" MAGI³C-VDRM_LGA-12EP 102,11.1 r270 top
IC3 "93AA66C-I/SN" SO-8N 123.4,18.9 r90 top
IC4 "LTC4296AUK-1#PBF" "QFN-48 7x7MM" 66.5,20.5 r0 top value=LTC4296AUK-1
IC5 "STM32G030C8T6" "QFP-48 7x7MM" 78,43.9 r270 top
IC6 "LTC4359CDCB#TRMPBF" "DFN-6 2X3_0.5" 47.6,10.4 r180 top value=LTC4359CDCB
IC9 "ADIN1100CCPZ-R7" "QFN-40 6x6MM" 52.1,65 r270 top value=ADIN1100CCPZ
IC10 "74LVC1G14GV,125" SOT-23-5 96.6,81.8 r0 top value=74LVC1G14GV
IC11 "TPS3125L30DBVR" SOT-23-5 91.2,77.3 r90 top value=TPS3125L30
IC12 "24FC512-I/SN" SO-8 113.1,50.5 r90 top value=24FC512
IC13 "LAN9355I/ML" "QFN-88 12X12MM" 112.2,67 r270 top value=LAN9355
L1 "744870471_(2)" "Inductor_WE-DD 1280" 36.1,41.3 r0 top value=2x470uH
L2 "7442335600" INDUCTOR_WE-CNSW-HF-0504 138.4,30.1 r180 top value="60R @ 100MHz"
L3 "7442335600" INDUCTOR_WE-CNSW-HF-0504 138.4,34.1 r180 top value="60R @ 100MHz"
L4 "74404032033" "Inductor_WE-LQS 3015" 116.9,25.3 r270 top value=3.3uH
L5 "744232090" INDUCTOR_WE-CNSW-1206 137.4,32.1 r180 top value="90R @ 100MHz"
L6 "744224" Inductor_WE-SL2 21.9,46.1 r270 top value=2x250uH
L8 "74404064220" "Inductor_WE-LQS 6045" 31.7,37.5 r180 bottom value=22uH
L10 "74404064220" "Inductor_WE-LQS 6045" 31.7,45.1 r180 bottom value=22uH
L11 "74404032220" "Inductor_WE-LQS 3015" 92.9,13.3 r0 top value=22uH
L12 "74404042047" Inductor_WE-LQS-4018 112,8.1 r0 top value=4.7uH
L13 "744222" Inductor_WE-SL2 31.4,16.1 r0 top value=2x1000uH
LGATE "PartNumber" "TESTPOINT 1.5mm"#1 71.3,8.7 r0 top value=1.5mm
Logo1 "Wurth_994x400" Wurth_994x400 12.1,22.7 r0 top
LSNS "PartNumber" "TESTPOINT 1.5mm"#1 58.3,7 r90 top value=1.5mm
OUTP1 "PartNumber" "TESTPOINT 1.5mm"#1 63,28.3 r90 bottom value=1.5mm
OUTP2 "PartNumber" "TESTPOINT 1.5mm"#1 66,28.3 r90 bottom value=1.5mm
OUTP3 "PartNumber" "TESTPOINT 1.5mm"#1 69,28.3 r90 bottom value=1.5mm
OUTP4 "PartNumber" "TESTPOINT 1.5mm"#1 72,28.3 r90 bottom value=1.5mm
R2 "RC0603FR-075K1L" CR1608-0603 140.8,28 r180 top value=5k1
R3 "RC0603FR-075K1L" CR1608-0603 59.8,15.1 r180 top value=5k1
R4 "560112116020" CR1608-0603 110.1,13 r90 top value=330R
R5 "560112116005" CR1608-0603 128.8,24.7 r180 top value=10k
R6 "560112116005" CR1608-0603 133.5,36.4 r270 top value=10k
R7 "560112116091" CR1608-0603 116.7,39.4 r180 top value=2k
R8 "RC0603FR-0710KL" CR1608-0603 128.8,23.2 r0 top value=10k
R9 "RC0603FR-0724K3L" CR1608-0603 68.2,12.7 r270 top value=24k3
R10 "RC0603FR-07402KL" CR1608-0603 97,15.2 r180 top value=402k
R11 "560112116040" CR1608-0603 130.5,37.2 r0 top value=12k
R12 "560112116005" CR1608-0603 135.1,36.4 r90 top value=10k
R13 "RC1206FR-0749R9L" CR3216-1206 57.7,35.4 r0 bottom value=49R9
R14 "560112132008" CR3216-1206 57.6,39.2 r90 bottom value=20R
R15 "RC1206FR-075R1L" CR3216-1206 63.1,47.7 r0 bottom value=5R1
R16 "RC0603FR-075K1L" CR1608-0603 63,41.3 r0 bottom value=5k1
R17 "560112116005" CR1608-0603 117.7,19.5 r180 top value=10k
R18 "560112116005" CR1608-0603 128.5,17.9 r90 top value=10k
R19 "RC0805JR-070RL" CR2012-0805 141.8,2.5 r270 top value=0R
R20 "RC0805JR-070RL" CR2012-0805 128.8,81.4 r90 top value=0R
R21 "RC0805JR-070RL" CR2012-0805 18.8,84 r90 top value=0R
R22 "RC0805JR-070RL" CR2012-0805 36,2.5 r270 top value=0R
R23 "RC0805JR-070RL" CR2012-0805 112,2.5 r270 top value=0R
R24 "RC1210FR-0749K9L" CR3225-1210 80.6,6.5 r0 top value=49k9
R25 "560112132002" CR3216-1206 68.7,7.1 r90 top value=1R
R26 "560112116004" CR1608-0603 55.1,43.7 r0 bottom value=100k
R27 "RC0603FR-075K1L" CR1608-0603 63.1,49.8 r0 bottom value=5k1
R28 "560112116017" CR1608-0603 100.2,17.3 r0 top value=5k6
R30 "560112116005" CR1608-0603 65.6,40.5 r270 bottom value=10k
R31 "560112116112" CR1608-0603 59.6,46.2 r90 bottom value=49k9
R32 "RC1206FR-075R1L" CR3216-1206 63,35.4 r180 bottom value=5R1
R33 "560112116004" CR1608-0603 89.1,26.3 r270 bottom value=100k
R34 "RC0603FR-07137KL" CR1608-0603 97,16.6 r180 top value=137k
R35 "560112116004" CR1608-0603 45,30.4 r0 top value=100k
R36 "560112132034" CR3216-1206 45,24.7 r180 top value=100k
R37 "560112116004" CR1608-0603 59.8,12.3 r0 top value=100k
R38 "RC0603FR-07100KL" CR1608-0603 60.6,11.5 r90 bottom value=100k
R39 "560112116006" CR1608-0603 67.2,46.1 r0 top value=4k7
R40 "560112116020" CR1608-0603 70.6,38.1 r180 top value=330R
R41 "" CR3225-1210 47.3,17.1 r180 bottom value=TBE
R42 "560112120020" CR2012-0805 14.3,63.4 r90 top value=100R
R43 "560112116014" CR1608-0603 49.8,8.1 r270 top value=1k
R52 "560112116006" CR1608-0603 62.7,57.525 r90 bottom value=4k7
R53 "560112116006" CR1608-0603 65.2,57.525 r90 bottom value=4k7
R54 "560112116006" CR1608-0603 67.8,57.525 r90 bottom value=4k7
R55 "560112116006" CR1608-0603 70.3,57.525 r90 bottom value=4k7
R56 "560112116006" CR1608-0603 72.9,57.525 r90 bottom value=4k7
R57 "560112116006" CR1608-0603 75.4,57.525 r90 bottom value=4k7
R58 "560112116006" CR1608-0603 77.9,57.525 r90 bottom value=4k7
R59 "560112116006" CR1608-0603 80.4,57.525 r90 bottom value=4k7
R60 "560112116006" CR1608-0603 56.7,70.8 r0 bottom value=4k7
R61 "560112116005" CR1608-0603 51.1,70.7 r180 top value=10k
R62 "560112116006" CR1608-0603 51.9,72.9 r270 top value=4k7
R63 "560112116005" CR1608-0603 56.6,72.9 r90 top value=10k
R64 "560112116133" CR1608-0603 41.4,69.2 r270 top value=49R9
R65 "RC0603FR-075K1L" CR1608-0603 43,69.2 r270 top value=5k1
R66 "560112116005" CR1608-0603 42.2,65.3 r0 top value=10k
R67 "560112116005" CR1608-0603 42.2,66.8 r180 top value=10k
R68 "RC0603FR-075K1L" CR1608-0603 43,62.9 r90 top value=5k1
R69 "560112116133" CR1608-0603 41.4,62.9 r90 top value=49R9
R70 "560112116038" CR1608-0603 46.6,55.6 r0 top value=1k5
R71 "560112116038" CR1608-0603 46.6,54.1 r0 top value=1k5
R72 "560112116006" CR1608-0603 99.1,77.3 r90 top value=4k7
R73 "560112116005" CR1608-0603 86.1,81.6 r270 top value=10k
R74 "560112116091" CR1608-0603 99.1,81.7 r270 top value=2k
R75 "560112116009" CR1608-0603 87.7,81.6 r270 top value=100R
R76 "560112116014" CR1608-0603 94,77.3 r270 top value=1k
R77 "560112116133" CR1608-0603 133.8,70.2 r180 bottom value=49R9
R78 "560112116133" CR1608-0603 133.8,67.7 r180 bottom value=49R9
R79 "560112116133" CR1608-0603 133.8,63.1 r180 bottom value=49R9
R80 "560112116133" CR1608-0603 133.8,61.5 r180 bottom value=49R9
R81 "RC0603FR-070RL" CR1608-0603 133.8,66.2 r180 bottom value=0R
R82 "560112116005" CR1608-0603 110.3,79.2 r90 top value=10k
R83 "RC0603FR-0712K1L" CR1608-0603 122.2,66.6 r0 top value=12k1
R84 "560112116005" CR1608-0603 112.2,79.2 r270 top value=10k
R85 "560112116091" CR1608-0603 107.5,51.3 r0 top value=2k
R86 "560112116091" CR1608-0603 107.5,52.8 r0 top value=2k
R87 "560112116006" CR1608-0603 107.5,49.8 r180 top value=4k7
R88 "560112116005" CR1608-0603 108.3,79.2 r90 top value=10k
R89 "560112116005" CR1608-0603 117.1,57.6 r270 top value=10k
R90 "560112116020" CR1608-0603 128.7,68.7 r180 bottom value=330R
R91 "560112116020" CR1608-0603 128.7,60.3 r180 bottom value=330R
R92 "560112116020" CR1608-0603 125.7,57.6 r270 top value=330R
R93 "560112116020" CR1608-0603 121.3,57.6 r90 top value=330R
R94 "RC0603FR-070RL" CR1608-0603 94.3,72.6 r0 top value=0R
R95 "RC0603FR-070RL" CR1608-0603 94.3,70.8 r0 top value=0R
R96 "RC0603FR-070RL" CR1608-0603 94.3,69 r0 top value=0R
R97 "RC0603FR-070RL" CR1608-0603 94.3,67.2 r0 top value=0R
R98 "RC0603FR-070RL" CR1608-0603 94.3,63.6 r0 top value=0R
R99 "RC0603FR-070RL" CR1608-0603 94.3,65.4 r0 top value=0R
R100 "560112116005" CR1608-0603 89.1,72.6 r0 top value=10k
R101 "560112116005" CR1608-0603 89.1,70.8 r0 top value=10k
R102 "560112116005" CR1608-0603 89.1,69 r0 top value=10k
R103 "560112116005" CR1608-0603 89.1,67.2 r0 top value=10k
R104 "560112116005" CR1608-0603 89.1,63.6 r0 top value=10k
R105 "560112116005" CR1608-0603 89.1,65.4 r0 top value=10k
R106 "RC0603FR-070RL" CR1608-0603 92.6,72.6 r0 top value=0R
R107 "RC0603FR-070RL" CR1608-0603 92.6,70.8 r0 top value=0R
R108 "RC0603FR-070RL" CR1608-0603 92.6,69 r0 top value=0R
R109 "RC0603FR-070RL" CR1608-0603 92.6,67.2 r0 top value=0R
R110 "RC0603FR-070RL" CR1608-0603 92.6,63.6 r0 top value=0R
R111 "RC0603FR-070RL" CR1608-0603 92.6,65.4 r0 top value=0R
R112 "560112116034" CR1608-0603 106.2,77.3 r90 top value=33R
R113 "560112116034" CR1608-0603 104.4,77.3 r90 top value=33R
R114 "560112116034" CR1608-0603 102.7,61.7 r0 top value=33R
R115 "560112116034" CR1608-0603 99,70.4 r180 top value=33R
R116 "560112116034" CR1608-0603 99,61.7 r0 top value=33R
R117 "560112116034" CR1608-0603 102.7,70.4 r180 top value=33R
R118 "560112116034" CR1608-0603 102.7,64.1 r0 top value=33R
R119 "560112116034" CR1608-0603 99,65.4 r0 top value=33R
R120 "560112116034" CR1608-0603 102.6,77.3 r90 top value=33R
R121 "560112116034" CR1608-0603 99,63.5 r0 top value=33R
R122 "560112116034" CR1608-0603 108.3,57.6 r270 top value=33R
R123 "560112116034" CR1608-0603 109.9,57.6 r270 top value=33R
R124 "560112116034" CR1608-0603 102.7,66.6 r0 top value=33R
R125 "560112116034" CR1608-0603 109.9,57.6 r270 bottom value=33R
R126 "560112116034" CR1608-0603 99,68.5 r0 top value=33R
R127 "560112116034" CR1608-0603 108.3,57.6 r270 bottom value=33R
R128 "560112116034" CR1608-0603 102.7,68.5 r0 top value=33R
R129 "560112116034" CR1608-0603 106.7,57.6 r270 top value=33R
R130 "560112116034" CR1608-0603 102.7,72.6 r0 top value=33R
R131 "560112116034" CR1608-0603 99,72.6 r0 top value=33R
R132 "RC0603FR-070RL" CR1608-0603 94.3,58.9 r0 top value=0R
R133 "RC0603FR-070RL" CR1608-0603 94.3,57.1 r0 top value=0R
R134 "RC0603FR-070RL" CR1608-0603 94.3,55.3 r0 top value=0R
R135 "RC0603FR-070RL" CR1608-0603 94.3,53.5 r0 top value=0R
R136 "RC0603FR-070RL" CR1608-0603 94.3,49.9 r0 top value=0R
R137 "RC0603FR-070RL" CR1608-0603 94.3,51.7 r0 top value=0R
R138 "560112116005" CR1608-0603 89.1,58.9 r0 top value=10k
R139 "560112116005" CR1608-0603 89.1,57.1 r0 top value=10k
R140 "560112116005" CR1608-0603 89.1,55.3 r0 top value=10k
R141 "560112116005" CR1608-0603 89.1,53.5 r0 top value=10k
R142 "560112116005" CR1608-0603 89.1,49.9 r0 top value=10k
R143 "560112116005" CR1608-0603 89.1,51.7 r0 top value=10k
R144 "RC0603FR-070RL" CR1608-0603 92.6,58.9 r0 top value=0R
R145 "RC0603FR-070RL" CR1608-0603 92.6,57.1 r0 top value=0R
R146 "RC0603FR-070RL" CR1608-0603 92.6,55.3 r0 top value=0R
R147 "RC0603FR-070RL" CR1608-0603 92.6,53.5 r0 top value=0R
R148 "RC0603FR-070RL" CR1608-0603 92.6,49.9 r0 top value=0R
R149 "RC0603FR-070RL" CR1608-0603 92.6,51.7 r0 top value=0R
R150 "560112116038" CR1608-0603 102.9,50.4 r270 top value=1k5
R151 "560112116005" CR1608-0603 100.8,50.4 r90 top value=10k
R152 "560112116005" CR1608-0603 102.9,57.6 r270 top value=10k
R153 "RC0603FR-070RL" CR1608-0603 97.6,32.2 r180 bottom value=0R
R154 "560112116133" CR1608-0603 96,29.2 r180 top value=49R9
R155 "560112116133" CR1608-0603 96,32.2 r180 top value=49R9
R156 "560112116133" CR1608-0603 96,35.2 r180 top value=49R9
R157 "560112116133" CR1608-0603 96,38.2 r180 top value=49R9
R158 "RC0805FR-0775RL" CR2012-0805 111.3,29 r180 bottom value=75R
R159 "RC0805FR-0775RL" CR2012-0805 111.3,37.9 r180 bottom value=75R
R160 "CRCW12060000Z0EA" CR3216-1206 104.3,28.9 r180 bottom value=0R
R161 "CRCW12060000Z0EA" CR3216-1206 104.3,31.4 r180 bottom value=0R
R162 "RC0603FR-070RL" CR1608-0603 124.8,72.2 r0 top value=0R
R198 "CRCW12060000Z0EA" CR3216-1206 104.3,35.4 r180 bottom value=0R
R199 "CRCW12060000Z0EA" CR3216-1206 104.3,37.9 r180 bottom value=0R
RSH0 "RL1206FR-070R24L" CR3216-1206 51.55,32.75 r90 top value=0R24
RSH1 "CRCW12060000Z0EA" CR3216-1206 58.05,32.75 r90 top value=0R
RSH2 "CRCW12060000Z0EA" CR3216-1206 64.55,32.75 r90 top value=0R
RSH3 "CRCW12060000Z0EA" CR3216-1206 71.05,32.75 r90 top value=0R
RSH4 "CRCW12060000Z0EA" CR3216-1206 77.55,32.75 r90 top value=0R
RSL0 "RL1206FR-070R062L" CR3216-1206 80.6,12 r0 top value=0R062
RSL1 "CRCW12060000Z0EA" CR3216-1206 80.6,15.6 r0 top value=0R
RSL2 "CRCW12060000Z0EA" CR3216-1206 80.6,19.2 r0 top value=0R
RSL3 "CRCW12060000Z0EA" CR3216-1206 80.6,22.8 r0 top value=0R
RSL4 "CRCW12060000Z0EA" CR3216-1206 80.6,26.4 r0 top value=0R
S1 "418121270808" 418121270808 71.6,65.625 r0 top
S2 "434153017835" 434153017835 91.5,81.7 r180 top
S3 "434153017835" 434153017835 70.7,52.1 r180 top
S4 "434153017835" 434153017835 67.2,42.5 r270 top
SCCPI "PartNumber" "TESTPOINT 1.5mm"#1 70.3,43.8 r90 top value=1.5mm
SCCPO "PartNumber" "TESTPOINT 1.5mm"#1 70.3,46.2 r90 top value=1.5mm
Sign1 "ESD_380x350" ESD_380x351 21.4,72.496 r0 top
Sign2 "WEEE_275x400" WEEE_275x400 35.34,69.767 r180 bottom
Sign3 "CE_412x295" CE_412x295 118.8,11.7 r180 bottom
SW0 "PartNumber" "TESTPOINT 1.5mm"#1 61.5,10.3 r90 top value=1.5mm
SW1 "PartNumber" "TESTPOINT 1.5mm"#1 61.5,7.8 r90 top value=1.5mm
SW2 "PartNumber" "TESTPOINT 1.5mm"#1 61.5,5.3 r90 top value=1.5mm
SW3 "PartNumber" "TESTPOINT 1.5mm"#1 64,7.8 r90 top value=1.5mm
SW4 "PartNumber" "TESTPOINT 1.5mm"#1 64,5.3 r90 top value=1.5mm
T1 "749070011" 749070011_WE-PoDL 22.2,63.07 r180 top
T2 "PSMN075-100MSEX" "LFPAK33 (SOT1210)" 51.5,38.1 r180 top
T3 "BSS123LT1G" SOT-23 54.8,49.8 r270 bottom value=BSS123
T4 "BSS138LT1G" SOT-23 96.6,77.6 r0 top
T5 "BSS123LT1G" SOT-23 62.7,38.7 r270 bottom value=BSS123
T6 "MMBTA06LT1G" SOT-23 54.8,46.3 r270 bottom value=MMBTA06L
T7 "PSMN020-100YS,115" "LFPAK56 (SOT669)" 74.1,12.4 r270 top value=PSMN020-100YS
T8 "MMBT3904LT1G" SOT-23 59.2,49.8 r90 bottom value=MMBT3904
T9 "MMBT3904LT1G" SOT-23 69.3,36.2 r180 bottom value=MMBT3904
T10 "BSS123LT1G" SOT-23 45.2,27.8 r270 top value=BSS123
T11 "BUK7Y53-100B,115" "LFPAK56 (SOT669)" 48.55,16.45 r270 top value=BUK7Y53-100B
TP1 "PartNumber" "TESTPOINT 1.5mm"#2 119.2,44.5 r0 top value=1.5mm
TP2 "PartNumber" "TESTPOINT 1.5mm"#2 88.9,14.9 r90 top value=1.5mm
TP3 "PartNumber" "TESTPOINT 1.5mm"#2 54.9,74.4 r90 top value=1.5mm
TP4 "PartNumber" "TESTPOINT 1.5mm"#2 54.9,72.1 r90 top value=1.5mm
TP5 "PartNumber" "TESTPOINT 1.5mm"#2 114.3,79.4 r90 top value=1.5mm
TP6 "PartNumber" "TESTPOINT 1.5mm"#2 117.1,54.8 r90 top value=1.5mm
TP7 "PartNumber" "TESTPOINT 1.5mm"#2 102.9,52.8 r90 top value=1.5mm
TP8 "PartNumber" "TESTPOINT 1.5mm"#2 100.8,52.8 r90 top value=1.5mm
TP9 "PartNumber" "TESTPOINT 1.5mm"#2 100.8,56.8 r90 top value=1.5mm
TP10 "PartNumber" "TESTPOINT 1.5mm"#2 116.2,8.1 r90 top value=1.5mm
TP11 "PartNumber" "TESTPOINT 1.5mm"#2 116.2,13.9 r90 top value=1.5mm
VAR1 "82551600" CV3216-1206 11.7,69.4 r270 top
VAR2 "82551600" CV3216-1206 151.3,22.8 r90 top
X1 "632723300011" 632723300011_USB_TypeC 155,32.1 r90 top locked value="USB-C Receptacle"
X2 "09452812810" 09452812810 5.3,40.9 r270 top value="SPE PCB connector"
X3 "691322110003" 691322110003 8.2,59.5 r90 top value="Plug-in Terminal / 3P"
X4 "691502710002" WE-5027-02P 21.525,3.8 r0 top value="Screw Terminal / 2P"
X5 "61300211121" HDR1X2 45.2,43.7 r90 top value="Male Header 1x2"
X6 "61300311121" HDR1X3 55.14,54.9 r180 top value="Male Header 1x3"
X7 "74990112116A" RJ45_74990112116A 145.1,65.8 r90 top locked
X8 "7490100110A" 7490100110A 104.375,33.4 r90 top
X9 "61300311121" HDR1X3 86.4,39.96 r90 top value="Male Header 1x3"
X10 "61300211121" HDR1X2 45.2,33.82 r90 top value="Male Header 1x2"
X11 "61300611121" HDR1X6 86.4,22.88 r90 top value="Male Header 1x6"
X12 "61300821121" HDR2X4 139,48.5 r0 top value="Male Header 2x4"
Y1 "830055299" CRYSTAL_3225 125.9,45.7 r180 top value=25MHz
Y2 "830055299" CRYSTAL_3225 46.3,72.9 r180 top value=25MHz
Y3 "830055299" CRYSTAL_3225 120.6,78.8 r180 top value=25MHz
Y4 "830108313809" CRYSTAL_3225 77.85,52.2 r180 top value=8MHz
Z1 "DDZ9699-7" SOD-123 47.5,12 r270 bottom value=12V

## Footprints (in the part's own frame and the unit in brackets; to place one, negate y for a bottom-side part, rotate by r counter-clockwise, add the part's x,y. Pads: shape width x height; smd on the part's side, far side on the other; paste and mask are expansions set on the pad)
2038-XX [mm]
  rect 1.6x5.3 smd: 1(-3.3,0) 2(3.3,0) 3(0,0)
  silkscreen extent -2.3,-2.5 2.3,2.5, body extent -3.75,-2.5 3.75,2.5, height 5.3
749070011_WE-PoDL [mm]
  rect 0.7x1.5 smd: 1(-1.905,-4.25) 2(-0.635,-4.25) 3(0.635,-4.25) 4(1.905,-4.25) 5(1.905,4.25) 6(0.635,4.25) 7(-0.635,4.25) 8(-1.905,4.25)
  silkscreen extent -3.2,-4.2 3.05,3.25, body extent -3.25,-4.2 3.25,4.3, height 5.46
7490100110A [mm] "10/100 Base-T SMT  Transformer"
  rect 0.64x1.91 smd paste+0: 1(-4.445,-4.385) 2(-3.175,-4.385) 3(-1.905,-4.385) 4(-0.635,-4.385) 5(0.635,-4.385) 6(1.905,-4.385) 7(3.175,-4.385) 8(4.445,-4.385) 9(4.445,4.385) 10(3.175,4.385) 11(1.905,4.385) 12(0.635,4.385) 13(-0.635,4.385) 14(-1.905,4.385) 15(-3.175,4.385) 16(-4.445,4.385)
  silkscreen extent -6.35,-5.61 6.35,4.4, body extent -6.35,-4.7 6.35,4.7, height 6.35
09452812810 [mm] "SPE PCB connector"
  round 1.4 hole 0.9: 1(1.4,7.15) 2(-1.4,7.15)
  round 1.5 hole 1: SH(-4.45,0) SH(-3.8,9.75) SH(3.8,9.75) SH(4.45,0)
  silkscreen extent -4.75,-5.1 4.75,9.9, body extent -4.6,-5 4.6,9.9, height 5.87
418121270808 [mm] "DIP SWITCH"
  rect 1.1x2.2 smd: 1(-8.87,-4.4) 2(-6.33,-4.4) 3(-3.81,-4.4) 4(-1.27,-4.4) 5(1.27,-4.4) 6(3.79,-4.4) 7(6.33,-4.4) 8(8.87,-4.4) 9(8.87,4.4) 10(6.33,4.4) 11(3.79,4.4) 12(1.27,4.4) 13(-1.27,4.4) 14(-3.81,4.4) 15(-6.33,4.4) 16(-8.87,4.4)
  silkscreen extent -10.63,-3 10.63,3, body extent -10.63,-4.9 10.63,4.9, height 4.31
434153017835 [mm]
  rect 1.2x1 smd: 1(-1.7,0.8) 2(-1.7,-0.8) 3(1.7,0.8) 4(1.7,-0.8)
  silkscreen extent -1.75,-1.5 1.75,1.5, body extent -2.15,-1.45 2.15,1.45, height 1.7
632723300011_USB_TypeC [mm] "WR-COM USB 3.1 Horizontal"
  rect 0.3x1.2 smd paste+0 mask+0.064: A1(-2.75,10.58) A2(-2.25,10.58) A3(-1.75,10.58) A4(-1.25,10.58) A5(-0.75,10.58) A6(-0.25,10.58) A7(0.25,10.58) A8(0.75,10.58) A9(1.25,10.58) A10(1.75,10.58) A11(2.25,10.58) A12(2.75,10.58)
  round 0.65 hole 0.4 paste+0 mask+0.051: B1(2,9.33) B1(2.8,9.33) B2(2.4,8.63) B3(1.6,8.63) B4(1.2,9.33) B5(0.8,8.63) B6(0.4,9.33) B7(-0.4,9.33) B8(-0.8,8.63) B9(-1.2,9.33) B10(-1.6,8.63) B11(-2.4,8.63) B12(-2.8,9.33) B12(-2,9.33)
  oval 1x1.6 hole 0.6 slot 1.2 at 90 deg paste+0 mask+0.127: SH1(-4.27,3.45) SH2(-4.27,8.18) SH3(4.27,3.45)
  oval 1x1.5 hole 0.6 slot 1.2 at 90 deg paste+0 mask+0.127: SH4(4.27,8.18)
  silkscreen extent -4.4,-0.95 4.4,10.25, body extent -4.37,-0.95 4.37,10.84, height 3.03
691322110003 [mm]
  round 2.3 hole 1.4: 1(-3.5,0) 2(0,0) 3(3.5,0)
  silkscreen extent -5.95,-1.2 5.95,8, body extent -5.95,-1.2 5.95,8, height 7.25
CC1005-0402 [mm]
  rect 0.5x0.6 smd mask+0.1: 1(-0.5,0) 2(0.5,0)
  silkscreen extent -0.15,-0.24 0.15,0.24, body extent -0.5,-0.25 0.5,0.25, height 0.49
CC1608-0603 [mil]
  rect 34x33.46 smd: 1(-32.5,0) 2(32.5,0)
  silkscreen extent -6,-13 6,13, body extent -31,-16 31,16, height 31
CC2012-0805 [mm]
  rect 0.8x1.3 smd: 1(-0.9,0) 2(0.9,0)
  silkscreen extent -0.28,-0.58 0.27,0.57, body extent -1,-0.63 1,0.63, height 0.59
CC3216-1206 [mm]
  rect 1.6x1.8 smd: 1(-1.4,0) 2(1.4,0)
  silkscreen extent -0.4,-0.77 0.4,0.77, body extent -1.6,-0.8 1.6,0.8, height 0.77
CC3225-1210 [mm]
  rect 1.6x2.7 smd: 1(-1.4,0) 2(1.4,0)
  silkscreen extent -0.4,-1.25 0.4,1.25, body extent -1.6,-1.25 1.6,1.25, height 2.5
CE_412x295 [mm]
  silkscreen extent 0,0 10.46,7.44
CF1608-0603 [mil]
  rect 34x33.46 smd: 1(-32.5,0) 2(32.5,0)
  silkscreen extent -6,-13 6,13, body extent -31,-16 31,16, height 37
CF2012-0805 [mm]
  rect 0.8x1.3 smd: 1(-0.9,0) 2(0.9,0)
  silkscreen extent -0.28,-0.58 0.27,0.57, body extent -1,-0.6 1,0.6, height 0.95
CR1608-0603 [mil]
  rect 34x33.46 smd: 1(-32.5,0) 2(32.5,0)
  silkscreen extent -6,-13 6,13, body extent -31,-16 31,16, height 18
CR2012-0805 [mm]
  rect 0.8x1.3 smd: 1(-0.9,0) 2(0.9,0)
  silkscreen extent -0.28,-0.58 0.28,0.58, body extent -1,-0.62 1,0.63, height 0.5
CR3216-1206 [mm]
  rect 1.3x1.8 smd: 1(-1.35,0) 2(1.35,0)
  silkscreen extent -0.4,-0.77 0.4,0.78, body extent -1.6,-0.8 1.6,0.8, height 0.55
CR3225-1210 [mm]
  rect 1.1x2.6 smd: 1(-1.45,0) 2(1.45,0)
  silkscreen extent -0.4,-1.2 0.4,1.2, body extent -1.6,-1.25 1.6,1.25, height 0.6
CRYSTAL_3225 [mm] "CRYSTAL_3225"
  rect 1.3x1.05 smd: 1(-1.15,-0.925) 2(1.15,-0.925) 3(1.15,0.925) 4(-1.15,0.925)
  silkscreen extent -1.65,-1.97 1.65,1.3, body extent -1.6,-1.25 1.6,1.25, height 1.05
CV3216-1206 [mm]
  rect 1.6x1.8 smd: 1(-1.4,0) 2(1.4,0)
  silkscreen extent -0.4,-0.77 0.4,0.78, body extent -1.6,-0.8 1.6,0.8, height 1.5
"DFN1210-6L 1.2X1.0" [mm]
  rect 0.2x0.6 smd mask+0.051: 1(-0.4,-0.475) 2(0,-0.475) 3(0.4,-0.475) 4(0.4,0.475) 5(0,0.475) 6(-0.4,0.475)
  silkscreen extent -0.75,-1.05 0.75,0.75, body extent -0.6,-0.5 0.6,0.5, height 0.45
"DFN-6 2X3_0.5" [mm]
  rect 0.25x0.7 smd paste-0.05 mask+0.07: 1(-0.5,-1.4) 2(0,-1.4) 3(0.5,-1.4) 4(0.5,1.4) 5(0,1.4) 6(-0.5,1.4)
  rect 1.35x1.65 smd mask+0.07: 7(0,0)
  silkscreen extent -1,-2.2 1,1.5, body extent -1.05,-1.56 1.05,1.56, height 0.8
ESD_380x351 [mm]
  silkscreen extent 0,0 9.65,8.89
HDR1X2 [mm]
  rect 1.8x1.8 hole 0.9: 1(0,0)
  round 1.8 hole 0.9: 2(2.54,0)
  silkscreen extent -1.27,-1.27 3.81,1.27, body extent -1.29,-1.27 3.79,1.27, height 8.54
HDR1X3 [mm]
  rect 1.8x1.8 hole 0.9: 1(0,0)
  round 1.8 hole 0.9: 2(2.54,0) 3(5.08,0)
  silkscreen extent -1.27,-1.27 6.35,1.27, body extent -1.27,-1.27 6.35,1.27, height 8.54
HDR1X6 [mm]
  rect 1.8x1.8 hole 0.9: 1(0,0)
  round 1.8 hole 0.9: 2(2.54,0) 3(5.08,0) 4(7.62,0) 5(10.16,0) 6(12.7,0)
  silkscreen extent -1.27,-1.27 13.97,1.27, body extent -1.27,-1.24 13.97,1.25, height 8.54
HDR2X4 [mm]
  rect 1.5x1.5 hole 0.9: 1(-3.81,-1.27)
  round 1.5 hole 0.9: 2(-3.81,1.27) 3(-1.27,-1.27) 4(-1.27,1.27) 5(1.27,-1.27) 6(1.27,1.27) 7(3.81,-1.27) 8(3.81,1.27)
  silkscreen extent -5.08,-2.54 5.08,2.54, body extent -5.08,-2.54 5.08,2.54, height 8.57
INDUCTOR_WE-CNSW-1206 [mm] "Common Mode Choke"
  rect 1.1x0.6 smd: 1(-1.35,0.5) 2(1.35,0.5) 3(1.35,-0.5) 4(-1.35,-0.5)
  silkscreen extent -2.05,-0.9 2,0.9, body extent -1.6,-0.8 1.6,0.8, height 1.8
INDUCTOR_WE-CNSW-HF-0504 [mm] "Common Mode Choke"
  rect 0.45x0.45 smd: 1(-0.525,0.375) 2(0.525,0.375) 3(0.525,-0.375) 4(-0.525,-0.375)
  silkscreen extent -0.9,-0.72 0.9,0.73, body extent -0.6,-0.5 0.6,0.5, height 0.9
"Inductor_WE-DD 1280" [mm] "WE-DD SMT Shielded Coupled  Inductor"
  rect 2.5x3.85 smd: 1(1.75,5) 2(-1.75,5) 3(-1.75,-5) 4(1.75,-5)
  silkscreen extent -6.25,-6.25 6.25,6.25, body extent -6.25,-6.25 6.25,6.25, height 8.7
"Inductor_WE-LQS 3015" [mm] "WE-LQS SMT Power Inductor"
  rect 1x2.7 smd: 1(-1.2,0) 2(1.2,0)
  silkscreen extent -0.5,-1.5 0.5,1.5, body extent -1.5,-1.5 1.5,1.5, height 1.5
"Inductor_WE-LQS 6045" [mm] "WE-LQS SMT Power Inductor"
  rect 1.8x5.7 smd: 1(-2.3,0) 2(2.3,0)
  silkscreen extent -1.1,-3 1.1,3, body extent -3,-3 3,3, height 4.55
Inductor_WE-LQS-4018 [mm]
  rect 1.5x3.6 smd: 1(-1.75,0) 2(1.75,0)
  silkscreen extent -0.65,-2 0.65,2, body extent -2,-2 2,2, height 1.9
Inductor_WE-SL2 [mm] "WE-SL2 SMD Common Mode Line  Filter"
  rect 2.4x1.3 smd: 1(-3.95,-1.27) 2(-3.95,1.27) 3(3.95,1.27) 4(3.95,-1.27)
  silkscreen extent -3.15,-3.15 3.15,3.15, body extent -4.6,-3 4.6,3, height 5
"LED1608 (0603) - BLUE" [mm]
  rect 0.8x0.8 smd: 1(-0.75,0) 2(0.75,0)
  silkscreen extent -1.65,-0.67 1.4,0.67, body extent -0.8,-0.4 0.8,0.4, height 0.61
"LED1608 (0603) - Green" [mm]
  rect 0.8x0.8 smd: 1(-0.75,0) 2(0.75,0)
  silkscreen extent -1.65,-0.67 1.4,0.67, body extent -0.81,-0.4 0.81,0.4, height 0.6
"LED1608 (0603) - Red" [mm]
  rect 0.8x0.8 smd: 1(-0.75,0) 2(0.75,0)
  silkscreen extent -1.65,-0.67 1.4,0.67, body extent -0.81,-0.4 0.81,0.4, height 0.6
"LED1608 (0603) - YELLOW" [mm]
  rect 0.8x0.8 smd: 1(-0.75,0) 2(0.75,0)
  silkscreen extent -1.65,-0.67 1.4,0.67, body extent -0.8,-0.4 0.8,0.4, height 0.6
"LED2012 (0805) - Green" [mm] "LED 0805"
  rect 1.1x1.3 smd: 1(-1.05,0) 2(1.05,0)
  silkscreen extent -2.1,-0.9 1.85,0.9, body extent -1.01,-0.63 1.01,0.63, height 1.1
"LFPAK33 (SOT1210)" [mm]
  rect 0.4x0.83 smd paste-0.05 mask+0.05: 1(-0.975,-1.93) 2(-0.325,-1.93) 3(0.325,-1.93) 4(0.975,-1.93)
  rect 0.4x0.75 smd paste-0.05 mask+0.05: mb(-0.975,1.18) mb(-0.325,1.18) mb(0.325,1.18) mb(0.975,1.18)
  rect 2.25x1.85 smd paste-5 mask+0.05: mb(0,0)
  body extent -1.64,-1.91 1.66,1.39, height 0.81
"LFPAK56 (SOT669)" [mm]
  rect 0.7x1.15 smd paste-0.05: 1(-1.905,-2.725)
  rect 0.7x1.15 smd paste-0.05 mask+0.075: 2(-0.635,-2.725) 3(0.635,-2.725) 4(1.905,-2.725)
  rect 4.7x1.5 smd paste-4.7 mask+0.075: mb(0,2.75)
  rect 4.2x3.2 smd paste-3.2 mask+0.075: mb(0,0.5)
  silkscreen extent -2.86,-2.81 2.75,2.73, body extent -2.4,-2.96 2.41,3.15, height 1
M3_VIA [mm]
  round 6 hole 3.2 mask+0.05: 0(0,0)
MAGI³C-VDRM_LGA-12EP [mm] "Variable Step Down LGA Module, SMT, body 10x6mm"
  rect 0.4x0.5 smd: 1(-4.65,-2.6) 2(-3.65,-2.6) 3(-2.65,-2.6) 4(-1.65,-2.6) 5(-0.65,-2.6) 8(-0.65,2.6) 9(-1.65,2.6) 10(-2.65,2.6) 11(-3.65,2.6) 12(-4.65,2.6)
  rect 1.5x1.5 smd: 6(4.1,-2.1) 7(4.1,2.1) 13(-3.05,0)
  silkscreen extent -5,-3.57 5,3, body extent -5,-3 5,3, height 3.02
"QFN-40 6x6MM" [mm]
  rect 0.85x0.3 smd mask+0.076: 1(-2.95,2.25) 2(-2.95,1.75) 3(-2.95,1.25) 4(-2.95,0.75) 5(-2.95,0.25) 6(-2.95,-0.25) 7(-2.95,-0.75) 8(-2.95,-1.25) 9(-2.95,-1.75) 10(-2.95,-2.25) 21(2.95,-2.25) 22(2.95,-1.75) 23(2.95,-1.25) 24(2.95,-0.75) 25(2.95,-0.25) 26(2.95,0.25) 27(2.95,0.75) 28(2.95,1.25) 29(2.95,1.75) 30(2.95,2.25)
  rect 0.3x0.85 smd mask+0.076: 11(-2.25,-2.95) 12(-1.75,-2.95) 13(-1.25,-2.95) 14(-0.75,-2.95) 15(-0.25,-2.95) 16(0.25,-2.95) 17(0.75,-2.95) 18(1.25,-2.95) 19(1.75,-2.95) 20(2.25,-2.95) 31(2.25,2.95) 32(1.75,2.95) 33(1.25,2.95) 34(0.75,2.95) 35(0.25,2.95) 36(-0.25,2.95) 37(-0.75,2.95) 38(-1.25,2.95) 39(-1.75,2.95) 40(-2.25,2.95)
  rect 3.6x3.6 smd: 41(0,0)
  silkscreen extent -3.5,2.88 -3.25,3.13, body extent -3.05,-3.05 3.05,3.05, height 0.8
"QFN-48 7x7MM" [mm] "QFN, 48-Leads, Body 7x7mm (max), Pitch 0.50mm, IPC Medium Density"
  rect 0.7x0.25 smd mask+0.076: 1(-3.4,2.75) 2(-3.4,2.25) 3(-3.4,1.75) 4(-3.4,1.25) 5(-3.4,0.75) 6(-3.4,0.25) 7(-3.4,-0.25) 8(-3.4,-0.75) 9(-3.4,-1.25) 10(-3.4,-1.75) 11(-3.4,-2.25) 12(-3.4,-2.75) 25(3.4,-2.75) 26(3.4,-2.25) 27(3.4,-1.75) 28(3.4,-1.25) 29(3.4,-0.75) 30(3.4,-0.25) 31(3.4,0.25) 32(3.4,0.75) 33(3.4,1.25) 34(3.4,1.75) 35(3.4,2.25) 36(3.4,2.75)
  rect 0.25x0.7 smd mask+0.076: 13(-2.75,-3.4) 14(-2.25,-3.4) 15(-1.75,-3.4) 16(-1.25,-3.4) 17(-0.75,-3.4) 18(-0.25,-3.4) 19(0.25,-3.4) 20(0.75,-3.4) 21(1.25,-3.4) 22(1.75,-3.4) 23(2.25,-3.4) 24(2.75,-3.4) 37(2.75,3.4) 38(2.25,3.4) 39(1.75,3.4) 40(1.25,3.4) 41(0.75,3.4) 42(0.25,3.4) 43(-0.25,3.4) 44(-0.75,3.4) 45(-1.25,3.4) 46(-1.75,3.4) 47(-2.25,3.4) 48(-2.75,3.4)
  rect 5.2x5.2 smd mask+0.076: 49(0,0)
  silkscreen extent -4.12,-3.5 3.5,3.5, body extent -3.51,-3.51 3.51,3.51, height 0.78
